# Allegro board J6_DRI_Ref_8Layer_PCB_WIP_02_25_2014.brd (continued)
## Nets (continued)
H_MMC2_DAT4_S1: RN30.4(R4A)
H_MMC2_DAT5: RN30.6(R3B) U52.M7(GPMC_A20/MMC2_DAT5/GPMC_A14/VIN)
H_MMC2_DAT5_S1: RN30.3(R3A)
H_MMC2_DAT6: RN30.7(R2B) U52.J5(GPMC_A21/MMC2_DAT6/GPMC_A15/VIN)
H_MMC2_DAT6_S1: RN30.2(R2A)
H_MMC2_DAT7: RN30.8(R1B) U52.K6(GPMC_A22/MMC2_DAT7/GPMC_A16/VIN)
H_MMC2_DAT7_S1: RN30.1(R1A)
H_MMC3_CLK: R859.1 U52.AD4(MMC3_CLK/USB3_ULPI_D5/VIN2B_D7/)
H_MMC3_CLK_S1: R859.2
H_MMC3_CMD: U52.AC4(MMC3_CMD/SPI3_SCLK/USB3_ULPI_D4)
H_MMC3_DAT0: U52.AC7(MMC3_DAT0/SPI3_D1/UART5_RXD/USB)
H_MMC3_DAT1: U52.AC6(MMC3_DAT1/SPI3_D0/UART5_TXD/USB)
H_MMC3_DAT2: U52.AC9(MMC3_DAT2/SPI3_CS0/UART5_CTSN/U)
H_MMC3_DAT3: U52.AC3(MMC3_DAT3/SPI3_CS1/UART5_RTSN/U)
H_MMC3_DAT4: U52.AC8(MMC3_DAT4/SPI4_SCLK/UART10_RXD/)
H_MMC3_DAT5: U52.AD6(MMC3_DAT5/SPI4_D1/UART10_TXD/US)
H_MMC3_DAT6: U52.AB8(MMC3_DAT6/SPI4_D0/UART10_CTSN/U)
H_MMC3_DAT7: U52.AB5(MMC3_DAT7/SPI4_CS0/UART10_RTSN/)
H_MMC4_CLK: R651.2 U52.E25(UART1_CTSN/UART9_RXD/MMC4_CLK/G)
H_MMC4_CLK_S1: R651.1
H_MMC4_CMD: U52.C27(UART1_RTSN/UART9_TXD/MMC4_CMD/G)
H_MMC4_DAT0: U52.D28(UART2_RXD/UART3_CTSN/UART3_RCTX)
H_MMC4_DAT1: U52.D26(UART2_TXD/UART3_RTSN/UART3_SD/M)
H_MMC4_DAT2: U52.D27(UART2_CTSN/UART3_IRRX/MMC4_DAT2)
H_MMC4_DAT3: U52.C28(UART2_RTSN/UART3_TXD/UART3_IRTX)
H_NMIN: R245.1 R632.2 U52.D21(NMIN)
H_ON_OFF: R216.2 U52.Y11(ON_OFF)
H_OSC0_RTN: C126.2 C128.2 U52.AF15(VSSA_OSC0)
H_OSC0_XIN: C128.1 U52.AE15(XI_OSC0) Y6.1
H_OSC0_XOUT: C126.1 U52.AD15(X0_OSC0) Y6.2
H_OSC1_RTN: C123.2 C124.2 U52.AC14(VSSA_OSC1) Y5.2 Y5.4
H_OSC1_XIN: C123.1 U52.AC15(XI_OSC1) Y5.1
H_OSC1_XOUT: C124.1 U52.AC13(XO_OSC1) Y5.3
H_OSCRTC_XIN: C113.1 U52.AE14(RTC_OSC_XI_CLKIN32) Y3.4
H_OSCRTC_XOUT: C106.1 U52.AD14(RTC_OSC_XO) Y3.1
H_PCIE_RXN0: U52.AG13(PCIE_RXN0)
H_PCIE_RXN1: U52.AG11(PCIE_RXN1)
H_PCIE_RXP0: U52.AH13(PCIE_RXP0)
H_PCIE_RXP1: U52.AH11(PCIE_RXP1)
H_PCIE_TXN0: U52.AG14(PCIE_TXN0)
H_PCIE_TXN1: U52.AG12(PCIE_TXN1)
H_PCIE_TXP0: U52.AH14(PCIE_TXP0)
H_PCIE_TXP1: U52.AH12(PCIE_TXP1)
H_POR_N: C550.1 R269.2 TP60.1(TP) U52.F22(PORZ) U62.4(Y)
H_QSPI1_CS0: R131.1 U18.7(C\S\)
H_QSPI1_D0: U18.15(SI/IO0) U52.U1(GPMC_A16/QSPI1_D0/VIN4A_D9/GPIO)
H_QSPI1_D1: U18.8(SO/IO1) U52.P3(GPMC_A17/QSPI1_D1/VIN4A_D10/GPI)
H_QSPI1_D2: R442.2 U18.9(W\P\/IO2) U52.U2(GPMC_A15/QSPI1_D2/VIN4A_D8/TIME)
H_QSPI1_D3: R128.2 U18.1(H\O\L\D\/IO3) U52.T2(GPMC_A14/QSPI1_D3/VIN4A_VSYNC0/)
H_QSPI1_RTCLK: R727.2 U52.R3(GPMC_A13/QSPI1_RTCLK/VIN4A_HSYN)
H_QSPI1_SCLK: R963.2 U52.R2(GPMC_A18/QSPI1_SCLK/VIN4A_D11/G)
H_QSPI1_SCLK_23254155: R727.1 R728.2
H_QSPI1_SCLK_S1: R963.1
H_QSPI1_SCLK_S1_23254130: R728.1 U18.16(SCLK)
H_RESET_N: C553.1 TP59.1(TP) U52.E23(RESETN)
H_RGMII0_RXC: R917.2 U52.U5(RGMII0_RXC/RMII1_TXEN/MII0_TXCL)
H_RGMII0_RXC_S1: R917.1
H_RGMII0_RXCTL: R918.2 U52.V5(RGMII0_RXCTL/RMII1_TXD1/MII0_TX)
H_RGMII0_RXCTL_S1: R918.1
H_RGMII0_RXD0: R919.2 U52.W2(RGMII0_RXD0/RMII0_TXD0/MII0_TXD)
H_RGMII0_RXD0_S1: R919.1
H_RGMII0_RXD1: R920.2 U52.Y2(RGMII0_RXD1/RMII0_TXD1/MII0_TXD)
H_RGMII0_RXD1_S1: R920.1
H_RGMII0_RXD2: R921.2 U52.V3(RGMII0_RXD2/RMII0_TXEN/MII0_TXE)
H_RGMII0_RXD2_S1: R921.1
H_RGMII0_RXD3: R922.2 U52.V4(RGMII0_RXD3/RMII1_TXD0/MII0_TXD)
H_RGMII0_RXD3_S1: R922.1
H_RGMII0_TD0: R925.2 U52.U6(RGMII0_TXD0/RMII0_RXD0/MII0_RXD)
H_RGMII0_TD0_S1: R925.1
H_RGMII0_TD1: R926.2 U52.V6(RGMII0_TXD1/RMII0_RXD1/MII0_RXD)
H_RGMII0_TD1_S1: R926.1
H_RGMII0_TD2: R927.2 U52.U7(RGMII0_TXD2/RMII0_RXER/MII0_RXE)
H_RGMII0_TD2_S1: R927.1
H_RGMII0_TD3: R928.2 U52.V7(RGMII0_TXD3/RMII0_CRS/MII0_CRS/)
H_RGMII0_TD3_S1: R928.1
H_RGMII0_TXC: R923.2 U52.W9(RGMII0_TXC/UART3_CTSN/RMII1_RXD)
H_RGMII0_TXC_S1: R923.1
H_RGMII0_TXCTL: R924.2 U52.V9(RGMII0_TXCTL/UART3_RTSN/RMII1_R)
H_RGMII0_TXCTL_S1: R924.1
H_RMII_50MHZ_CLK: R929.2 U52.U3(RMII_MHZ_50_CLK/VIN2A_D11/GPIO5)
H_RMII_50MHZ_CLK_S1: R929.1
H_RSTOUT_N: R256.2 R417.1 R650.2 R864.1 TP58.1(TP) U18.3(R\E\S\E\T\/RFU) U52.F23(RSTOUTN) U59.33(R\E\S\E\T\) U130.2(A) U132.8(RESETB)
H_RSV_Y5: U52.Y5(RSV_Y5)
H_SATA1_TXN0: U52.AG9(SATA1_RXP0) U52.AG10(SATA1_TXN0) U52.AG15(LJCB_CLKP)
H_SATA1_TXP0: U52.AH9(SATA1_RXN0) U52.AH10(SATA1_TXP0)
H_UART1_DBG_RX1: U52.B27(UART1_RXD/MMC4_SDCD/GPIO7_22)
H_UART1_DBG_TX1: U52.C26(UART1_TXD/MMC4_SDWP/GPIO7_23)
H_UART3_CTS: U52.G17(SPI2_D0/UART3_CTSN/UART5_RXD/GP)
H_UART3_RTS: U52.B24(SPI2_CS0/UART3_RTSN/UART5_TXD/G)
H_UART3_RXD: U52.A26(SPI2_SCLK/UART3_RXD/GPIO7_14)
H_UART3_TXD: U52.B22(SPI2_D1/UART3_TXD/GPIO7_15)
H_UART4_LIN_RXD: U52.B21(SPI1_CS2/UART4_RXD/MMC3_SDCD/SP)
H_UART4_LIN_TXD: U52.B20(SPI1_CS3/UART4_TXD/MMC3_SDWP/SP)
H_USB1_DM: FL1.4 U52.AC12(USB1_DM)
H_USB1_DP: FL1.1 U52.AD12(USB1_DP)
H_USB1_DRV_VBUS: R481.2 U36.4(EN) U52.AB10(USB1_DRVVBUS)
H_USB2_DM: FL4.4 U52.AF11(USB2_DM)
H_USB2_DP: FL4.1 U52.AE11(USB2_DP)
H_USB2_DRV_VBUS: R532.2 U43.4(EN) U52.AC10(USB2_DRVVBUS)
H_VIN1A_CLK0: R961.2 U52.AG8(VIN1A_CLK0/VOUT3_D16/VOUT3_FLD/)
H_VIN1A_CLK0_S1: R961.1
H_VIN1A_D0: U52.AE8(VIN1A_D0/VOUT3_D7/VOUT3_D23/UAR)
H_VIN1A_D1: U52.AD8(VIN1A_D1/VOUT3_D6/VOUT3_D22/UAR)
H_VIN1A_D2: U52.AG7(VIN1A_D2/VOUT3_D5/VOUT3_D21/UAR)
H_VIN1A_D3: U52.AH6(VIN1A_D3/VOUT3_D4/VOUT3_D20/UAR)
H_VIN1A_D4: U52.AH3(VIN1A_D4/VOUT3_D3/VOUT3_D19/EHR)
H_VIN1A_D5: U52.AH5(VIN1A_D5/VOUT3_D2/VOUT3_D18/EHR)
H_VIN1A_D6: U52.AG6(VIN1A_D6/VOUT3_D1/VOUT3_D17/EQE)
H_VIN1A_D7: U52.AH4(VIN1A_D7/VOUT3_D0/VOUT3_D16/EQE)
H_VIN1A_D8: U52.AG4(VIN1A_D8/VIN1B_D7/VOUT3_D15/KBD)
H_VIN1A_D9: U52.AG2(VIN1A_D9/VIN1B_D6/VOUT3_D14/KBD)
H_VIN1A_D10: U52.AG3(VIN1A_D10/VIN1B_D5/VOUT3_D13/KB)
H_VIN1A_D11: U52.AG5(VIN1A_D11/VIN1B_D4/VOUT3_D12/GP)
H_VIN1A_D12: U52.AF2(VIN1A_D12/VIN1B_D3/USB3_ULPI_D7)
H_VIN1A_D13: U52.AF6(VIN1A_D13/VIN1B_D2/USB3_ULPI_D6)
H_VIN1A_D14: U52.AF3(VIN1A_D14/VIN1B_D1/USB3_ULPI_D5)
H_VIN1A_D15: U52.AF4(VIN1A_D15/VIN1B_D0/USB3_ULPI_D4)
H_VIN1A_D16: U52.AF1(VIN1A_D16/VIN1B_D7/USB3_ULPI_D3)
H_VIN1A_D17: U52.AE3(VIN1A_D17/VIN1B_D6/USB3_ULPI_D2)
H_VIN1A_D18: U52.AE5(VIN1A_D18/VIN1B_D5/USB3_ULPI_D1)
H_VIN1A_D19: U52.AE1(VIN1A_D19/VIN1B_D4/USB3_ULPI_D0)
H_VIN1A_D20: U52.AE2(VIN1A_D20/VIN1B_D3/USB3_ULPI_NX)
H_VIN1A_D21: U52.AE6(VIN1A_D21/VIN1B_D2/USB3_ULPI_DI)
H_VIN1A_D22: U52.AD2(VIN1A_D22/VIN1B_D1/USB3_ULPI_ST)
H_VIN1A_D23: U52.AD3(VIN1A_D23/VIN1B_D0/USB3_ULPI_CL)
H_VIN1A_DE0: U52.AD9(VIN1A_DE0/VIN1B_HSYNC1/VOUT3_D1)
H_VIN1A_FLD0: U52.AF9(VIN1A_FLD0/VIN1B_VSYNC1/VOUT3_C)
H_VIN1A_HSYNC0: U52.AE9(VIN1A_HSYNC0/VIN1B_FLD1/VOUT3_H)
H_VIN1A_VSYNC0: U52.AF8(VIN1A_VSYNC0/VIN1B_DE1/VOUT3_VS)
H_VIN1B_CLK1: R960.2 U52.AH7(VIN1B_CLK1/VIN3A_CLK0/GPIO2_31)
H_VIN1B_CLK1_S1: R960.1
H_VIN2A_CLK0: R962.2 U52.E1(VIN2A_CLK0/VOUT2_FLD/EMU5/KBD_R)
H_VIN2A_CLK0_S1: R962.1
H_VIN2A_D0: U52.F2(VIN2A_D0/VOUT2_D23/EMU10/UART9_)
H_VIN2A_D1: U52.F3(VIN2A_D1/VOUT2_D22/EMU11/UART9_)
H_VIN2A_D2: U52.D1(VIN2A_D2/VOUT2_D21/EMU12/UART10)
H_VIN2A_D3: U52.E2(VIN2A_D3/VOUT2_D20/EMU13/UART10)
H_VIN2A_D4: U52.D2(VIN2A_D4/VOUT2_D19/EMU14/UART10)
H_VIN2A_D5: U52.F4(VIN2A_D5/VOUT2_D18/EMU15/UART10)
H_VIN2A_D6: U52.C1(VIN2A_D6/VOUT2_D17/EMU16/MII1_R)
H_VIN2A_D7: U52.E4(VIN2A_D7/VOUT2_D16/EMU17/MII1_R)
H_VIN2A_D8: U52.F5(VIN2A_D8/VOUT2_D15/EMU18/MII1_R)
H_VIN2A_D9: U52.E6(VIN2A_D9/VOUT2_D14/EMU19/MII1_R)
H_VIN2A_D10: U52.D3(VIN2A_D10/MDIO_MCLK/VOUT2_D13/K)
H_VIN2A_D11: U52.F6(VIN2A_D11/MDIO_D/VOUT2_D12/KBD_)
H_VIN2A_D12: U52.D5(VIN2A_D12/RGMII1_TXC/VOUT2_D11/)
H_VIN2A_D13: U52.C2(VIN2A_D13/RGMII1_TXCTL/VOUT2_D1)
H_VIN2A_D14: U52.C3(VIN2A_D14/RGMII1_TXD3/VOUT2_D9/)
H_VIN2A_D15: U52.C4(VIN2A_D15/RGMII1_TXD2/VOUT2_D8/)
H_VIN2A_D16: U52.B2(VIN2A_D16/VIN2B_D7/RGMII1_TXD1/)
H_VIN2A_D17: U52.D6(VIN2A_D17/VIN2B_D6/RGMII1_TXD0/)
H_VIN2A_D18: U52.C5(VIN2A_D18/VIN2B_D5/RGMII1_RXC/V)
H_VIN2A_D19: U52.A3(VIN2A_D19/VIN2B_D4/RGMII1_RXCTL)
H_VIN2A_D20: U52.B3(VIN2A_D20/VIN2B_D3/RGMII1_RXD3/)
H_VIN2A_D21: U52.B4(VIN2A_D21/VIN2B_D2/RGMII1_RXD2/)
H_VIN2A_D22: U52.B5(VIN2A_D22/VIN2B_D1/RGMII1_RXD1/)
H_VIN2A_D23: U52.A4(VIN2A_D23/VIN2B_D0/RGMII1_RXD0/)
H_VIN2A_DE0: U52.G2(VIN2A_DE0/VIN2A_FLD0/VIN2B_FLD1)
H_VIN2A_FLD0: U52.H7(VIN2A_FLD0/VIN2B_CLK1/VOUT2_CLK)
H_VIN2A_HSYNC0: U52.G1(VIN2A_HSYNC0/VIN2B_HSYNC1/VOUT2)
H_VIN2A_VSYNC0: U52.G6(VIN2A_VSYNC0/VIN2B_VSYNC1/VOUT2)
H_VOUT1_CLK: R834.2 U52.D11(VOUT1_CLK/VIN4A_FLD0/VIN3A_FLD0)
H_VOUT1_D0: RN20.5(R4B) U52.F11(VOUT1_D0/UART5_RXD/VIN4A_D16/VI)
H_VOUT1_D1: RN20.6(R3B) U52.G10(VOUT1_D1/UART5_TXD/VIN4A_D17/VI)
H_VOUT1_D2: RN20.7(R2B) U52.F10(VOUT1_D2/EMU2/VIN4A_D18/VIN3A_D)
H_VOUT1_D3: RN20.8(R1B) U52.G11(VOUT1_D3/EMU5/VIN4A_D19/VIN3A_D)
H_VOUT1_D4: RN21.5(R4B) U52.E9(VOUT1_D4/EMU6/VIN4A_D20/VIN3A_D)
H_VOUT1_D5: RN21.6(R3B) U52.F9(VOUT1_D5/EMU7/VIN4A_D21/VIN3A_D)
H_VOUT1_D6: RN21.7(R2B) U52.F8(VOUT1_D6/EMU8/VIN4A_D22/VIN3A_D)
H_VOUT1_D7: RN21.8(R1B) U52.E7(VOUT1_D7/EMU9/VIN4A_D23/VIN3A_D)
H_VOUT1_D8: RN22.5(R4B) U52.E8(VOUT1_D8/UART6_RXD/VIN4A_D8/VIN)
H_VOUT1_D9: RN22.6(R3B) U52.D9(VOUT1_D9/UART6_TXD/VIN4A_D9/VIN)
H_VOUT1_D10: RN22.7(R2B) U52.D7(VOUT1_D10/EMU3/VIN4A_D10/VIN3A_)
H_VOUT1_D11: RN22.8(R1B) U52.D8(VOUT1_D11/EMU10/VIN4A_D11/VIN3A)
H_VOUT1_D12: RN23.5(R4B) U52.A5(VOUT1_D12/EMU11/VIN4A_D12/VIN3A)
H_VOUT1_D13: RN23.6(R3B) U52.C6(VOUT1_D13/EMU12/VIN4A_D13/VIN3A)
H_VOUT1_D14: RN23.7(R2B) U52.C8(VOUT1_D14/EMU13/VIN4A_D14/VIN3A)
H_VOUT1_D15: RN23.8(R1B) U52.C7(VOUT1_D15/EMU14/VIN4A_D15/VIN3A)
H_VOUT1_D16: RN24.5(R4B) U52.B7(VOUT1_D16/UART7_RXD/VIN4A_D0/VI)
H_VOUT1_D17: RN24.6(R3B) U52.B8(VOUT1_D17/UART7_TXD/VIN4A_D1/VI)
H_VOUT1_D18: RN24.7(R2B) U52.A7(VOUT1_D18/EMU4/VIN4A_D2/VIN3A_D)
H_VOUT1_D19: RN24.8(R1B) U52.A8(VOUT1_D19/EMU15/VIN4A_D3/VIN3A_)
H_VOUT1_D20: RN25.5(R4B) U52.C9(VOUT1_D20/EMU16/VIN4A_D4/VIN3A_)
H_VOUT1_D21: RN25.6(R3B) U52.A9(VOUT1_D21/EMU17/VIN4A_D5/VIN3A_)
H_VOUT1_D22: RN25.7(R2B) U52.B9(VOUT1_D22/EMU18/VIN4A_D6/VIN3A_)
H_VOUT1_D23: RN25.8(R1B) U52.A10(VOUT1_D23/EMU19/VIN4A_D7/VIN3A_)
H_VOUT1_DE: R835.2 U52.B10(VOUT1_DE/VIN4A_DE0/VIN3A_DE0/SP)
H_VOUT1_HSYNC: R837.2 U52.C11(VOUT1_HSYNC/VIN4A_HSYNC0/VIN3A_)
H_VOUT1_VSYNC: R836.2 U52.E11(VOUT1_VSYNC/VIN4A_VSYNC0/VIN3A_)
H_WAKEUP0: TP54.1(TP) U52.AD17(WAKEUP0)
H_WAKEUP2: C535.1 R636.1 TP52.1(TP) U52.AB16(WAKEUP2)
H_WAKEUP3: R620.1 TP55.1(TP) U52.AC16(WAKEUP3)
H_XREF_CLK0: U52.D18(XREF_CLK0/MCASP2_AXR8/MCASP1_AX)
H_XREF_CLK1: U52.E17(XREF_CLK1/MCASP2_AXR9/MCASP1_AX)
H_XREF_CLK2: U52.B26(REF_CLK2/MCASP2_AXR10/MCASP1_AX)
H_XREF_CLK3: U52.C23(XREF_CLK3/MCASP2_AXR11/MCASP1_A)
HSGMLAN_BUS+: R238.1 R850.1 R941.1
HSGMLAN_BUS-: R255.2 R851.1 R942.1
I2C1_SCL: U50.6(SCL2) U59.1(SCL) U105.6(SCL) U117.1(SCL)
I2C1_SDA: U50.5(SDA2) U59.2(SDA) U105.5(SDA) U117.6(SDA)
I2C2_SCL: U3.8(SCL) U132.21(SCL)
I2C2_SDA: U3.9(SDA) U132.22(SDA)
I2C3_SCL: R865.1
I2C3_SDA: R420.2
I2C_EEPROM_WP: R569.2 R757.2 U105.7(WP)
INIC_DBG_ERR_BOOTN: P1.29
INIC_DBG_RSTN: P1.31
INIC_TCK: P1.35
INIC_TDI: P1.39
INIC_TDO: P1.37
INIC_TMS: P1.33
LIN_EN: R935.2
LIN_INH: TP76.1 U122.8(INH)
LIN_WAKE: TP77.1 U122.3(NWAKE)
LT_PMIC_RESET_OUT: R782.1 U101.3(A2)
LVL_SHIFT_V: U100.10(OE)
MCA1_ACLKX: U48.4(1A1)
MCA1_AFSX: U48.5(1A2)
MCA1_AXR0: U35.6(A4)
MCA1_AXR1: U48.6(2A1)
MCA7_AXR0: U35.9(A7)
MCA7_AXR1: U41.6(2A1)
MCA7_CLKX: U41.4(1A1)
MCA7_FSX: U41.5(1A2)
MCASP1_ENN: R599.2 R766.2 U35.22(OEN) U46.22(OEN) U48.14(2O\E\) U48.15(1O\E\)
MCU_DBG_RESETN: P1.24
MCU_DCAN_RX: U123.4(RXD)
MCU_DCAN_STB: R849.1 U123.8(STB)
MCU_DCAN_TX: R848.1 U123.1(TXD)
MCU_EVT0: P1.28
MCU_FLMD0: P1.26
MCU_FLMD1: P1.20
MCU_LIN_EN: R936.2
MCU_LIN_RXD: R934.2
MCU_LIN_TXD: R938.2
MCU_RDY: P1.30
MCU_RESET_OUT: R940.1
MCU_TCK: P1.36
MCU_TDI: P1.40
MCU_TDO: P1.38
MCU_TMS: P1.34
MCU_TRSTN: P1.32
MCU_TVD: P1.22
MIC_IN+: R801.1 R802.1
MIC_IN-: R800.1
MMC2_CLK: R433.2 U121.M6(CLK)
MMC2_CMD: R410.2 U121.M5(CMD)
MMC2_DAT0: R404.2 U121.A3(DAT0)
MMC2_DAT1: R422.2 U121.A4(DAT1)
MMC2_DAT2: R426.2 U121.A5(DAT2)
MMC2_DAT3: R406.2 U121.B2(DAT3)
MMC2_DAT4: R405.2 U121.B3(DAT4)
MMC2_DAT5: R414.2 U121.B4(DAT5)
MMC2_DAT6: R423.2 U121.B5(DAT6)
MMC2_DAT7: R428.2 U121.B6(DAT7)
MMC4_CLK: R587.2 U104.4(B)
MMC4_CMD: R520.2 U100.16(B4)
MMC4_DAT0: R521.2 U100.15(B5)
MMC4_DAT1: R522.2 U100.14(B6)
MMC4_DAT2: R523.2 U100.13(B7)
MMC4_DAT3: R524.2 U100.12(B8)
PCM_CLK: P9.52 U41.13(1B1)
PCM_DIN: P9.56 U41.11(2B1)
PCM_DOUT: P9.58 U35.15(B7)
PCM_FSYNC: P9.54 U41.12(1B2)
PHA: C300.1 L6.1 Q1.1(S1) Q1.2(S2) Q1.3(S3) Q3.5(D1) R126.2 U23.7(PHA)
PHB: C299.1 L7.1 Q2.1(S1) Q2.2(S2) Q2.3(S3) Q4.5(D1) R127.2 U23.32(PHB)
PMIC_32K_CLKOUT: R222.1 U45.M11(CLK32KGO)
PMIC_BOOT0: R518.1 R785.2 U45.L3(BOOT0)
PMIC_BOOT1: R513.1 R514.2 U45.K7(BOOT1)
PMIC_GPIO_0: R205.1 U45.B12(GPIO_0)
PMIC_GPIO_1: R191.1 R567.2 U45.C13(GPIO_1/VBUSDET)
PMIC_GPIO_2: R206.1 R783.1 U45.A12(GPIO_2/REGEN2)
PMIC_GPIO_3: R535.1 U45.H9(GPIO_3)
PMIC_GPIO_4_6: R473.1 U45.K10(GPIO_4/SYSEN1) U92.3(ON)
PMIC_GPIO_5: R565.1 U45.C10(GPIO_5/CLK32KGO)
PMIC_GPIO_6_4: R273.2 U45.N11(GPIO_6/SYSEN2) U63.15(EN)
PMIC_GPIO_7: R534.2 R537.1 U45.G9(GPIO_7/POWERHOLD)
PMIC_INT: R605.1 TP57.1(TP) U52.AC17(WAKEUP1) U101.2(A1)
PMIC_OFF: R204.2 R211.1 R216.1 U110.2(I)
PMIC_PWRDOWN: R483.1 R516.2 U45.K8(PWRDOWN)
PMIC_REGEN1: R784.1 TP41.1 U45.F8(REGEN1)
PMIC_RESET_IN: R153.2 R533.2 U37.1(R\E\S\E\T) U45.K9(RESET_IN)
PMIC_RESET_OUT: R782.2 R783.2 R784.2 U62.1(B)
PWRON: R208.2 R592.1 U45.G8(PWRON)
RPWRON: R194.2 R570.1 U45.C11(RPWRON)
RTC_PORZ: R530.2 U44.1(R\E\S\E\T) U52.AB17(RTC_PORZ)
SLEEP_CLK: P9.1 R222.2
SMPS_7: C409.2 L18.1
SMPS_8: C328.2 L9.1
SW1: L17.2 U45.E11(SMPS1_SW_1) U45.E12(SMPS1_SW_2) U45.E13(SMPS1_SW_3)
SW2: L15.2 U45.F11(SMPS2_SW_1) U45.F12(SMPS2_SW_2) U45.F13(SMPS2_SW_3)
SW3: L13.2 U45.J11(SMPS3_SW_1) U45.J12(SMPS3_SW_2) U45.J13(SMPS3_SW_3)
SW4: L16.2 U45.G1(SMPS4_SW_1) U45.G2(SMPS4_SW_2) U45.G3(SMPS4_SW_3)
SW5: L14.2 U45.H1(SMPS5_SW_1) U45.H2(SMPS5_SW_2) U45.H3(SMPS5_SW_3)
SW6: L11.2 U45.M5(SMPS6_SW_1) U45.N5(SMPS6_SW)
SW7: L18.2 U45.D1(SMPS7_SW_1) U45.D2(SMPS7_SW_2) U45.D3(SMPS7_SW_3)
SW8: L9.2 U45.M10(SMPS8_SW) U45.N10(SMPS8_SW_1)
SW9: L10.2 U45.M7(SMPS9_SW) U45.N7(SMPS9_SW_1)
TLIN1: R830.2 U122.6(LIN)
TPS43351_GC2: Q5.1(G) U23.4(GC2)
UART3_CTS: U35.8(A6)
UART3_RTS: U46.9(A7)
UART3_RXD: U35.7(A5)
UART3_TXD: U46.10(A8)
UART4_LIN_RXD: R933.2
UART4_LIN_TXD: R937.2
USB1_ID: U73.5(ID)
USB1_VBUS_OCN: R771.1 TP27.1 U36.5(OCN)
USB2_ID: U72.5(ID)
USB2_VBUS_OCN: R770.1 TP39.1 U43.5(OCN)
VAIC_AVDD_DAC3V3: C141.1 C142.1 C144.1 L21.1 U59.25(AVDD_DAC)
VAIC_DRVDD_3V3: C151.1 C152.1 C565.1 C566.1 C567.1 L22.1 U59.16(DRVDD.1) U59.17(DRVDD.2) U59.24(DRVDD.3)
VAIC_DVDD_1V8: C133.1 C134.1 U55.5(OUT) U59.36(DVDD.1)
VAIC_IOVDD_3V3: C130.1 C132.1 L19.2 U59.44(IOVDD)
VCAP_VBBLDO_DSPEVE: C477.1 U52.K9(CAP_VBBLDO_DSPEVE)
VCAP_VBBLDO_GPU: C501.1 U52.Y14(CAP_VBBLDO_GPU)
VCAP_VBBLDO_IVA: C519.1 U52.R20(CAP_VBBLDO_IVA)
VCAP_VBBLDO_MPU: C509.1 U52.J16(CAP_VBBLDO_MPU)
VCAP_VDDRAM_CORE1: C468.1 U52.L9(CAP_VDDRAM_CORE1)
VCAP_VDDRAM_CORE2: C517.1 U52.J19(CAP_VDDRAM_CORE2)
VCAP_VDDRAM_CORE3: C506.1 U52.Y15(CAP_VDDRAM_CORE3)
VCAP_VDDRAM_CORE4: C516.1 U52.P19(CAP_VDDRAM_CORE4)
VCAP_VDDRAM_CORE5: C512.1 U52.Y16(CAP_VDDRAM_CORE5)
VCAP_VDDRAM_DSPEVE1: C481.1 U52.J10(CAP_VDDRAM_DSPEVE1)
VCAP_VDDRAM_DSPEVE2: C462.1 U52.J9(CAP_VDDRAM_DSPEVE2)
VCAP_VDDRAM_GPU: C480.1 U52.Y13(CAP_VDDRAM_GPU)
VCAP_VDDRAM_IVA: C529.1 U52.T20(CAP_VDDRAM_IVA)
VCAP_VDDRAM_MPU1: C504.1 U52.K16(CAP_VDDRAM_MPU1)
VCAP_VDDRAM_MPU2: C520.1 U52.K19(CAP_VDDRAM_MPU2)
VDAC_3V3: C131.1 C153.1 C536.1 E8.3 L19.1 L21.2 L22.2 R249.1 R654.1 R659.1 R664.1 R668.1 U55.1(IN)
VEVM_1V8: C800.2 C810.2 E10.1 L23.1 P9.8 R548.1 R600.1 R842.2 R843.2 R844.2 R845.2 U132.20(DVDD)
VEVM_3V3: C67.1 C71.1 C74.1 C156.1 C293.1 C302.2 C330.1 C331.1 C338.2 C341.2 C342.2 C344.1 C346.2 C351.1 C353.2 C354.2 C358.1 C375.2 C376.2 C379.2 C380.2 C381.2 C404.1 C408.2 C441.1 C446.1 C459.2 C479.1 C513.2 C523.2 C573.1 C683.1 C696.1 C733.2 C734.2 C785.1 C786.1 C801.2 L2.2 L3.1 P5.1 P5.2 R1.2 R8.1 R14.1 R15.1 R16.1 R17.1 R18.1 R19.1 R20.1 R22.1 R80.1 R81.1 R82.1 R86.1 R87.1 R88.1 R89.1 R90.1 R91.1 R92.1 R93.1 R94.1 R95.1 R113.1 R114.1 R115.1 R128.1 R131.2 R134.1 R140.2 R143.2 R151.1 R153.1 R193.1 R194.1 R207.1 R208.1 R209.1 R272.1 R301.2 R302.2 R307.2 R327.1 R332.1 R407.2 R429.2 R442.1 R516.1 R519.1 R520.1 R521.1 R522.1 R523.1 R524.1 R528.1 R534.1 R549.1 R573.1 R575.1 R577.1 R581.1 R583.1 R584.1 R587.1 R596.2 R603.1 R618.1 R623.2 R624.1 R629.1 R632.1 R633.1 R650.1 R652.1 R757.1 R758.1 R759.1 R766.1 R770.2 R771.2 R774.1 R828.1 R829.1 R831.1 R839.1 R840.1 R841.1 R866.2 R867.2 R912.1 R914.2 R944.1 R945.1 R959.2 U6.5(VCC) U18.2(VCC) U18.14(VIO/RFU) U23.11(SA2) U35.1(VCCA) U37.6(VDD) U41.1(VCCA) U44.6(VDD) U45.C4(LDO9_IN) U45.C5(LDOLN_IN) U45.D11(SMPS1_IN_1) U45.D12(SMPS1_IN_2) U45.D13(SMPS1_IN_3) U45.E1(SMPS7_IN_B1_1) U45.E2(SMPS7_IN_B1_2) U45.E3(SMPS7_IN_B1_3) U45.F1(SMPS4_IN_1) U45.F2(SMPS4_IN_2) U45.F3(SMPS4_IN_3) U45.G11(SMPS2_IN_1) U45.G12(SMPS2_IN_2) U45.G13(SMPS2_IN_3) U45.H11(SMPS3_IN_1) U45.H12(SMPS3_IN_2) U45.H13(SMPS3_IN_3) U45.J1(SMPS5_IN_1) U45.J2(SMPS5_IN_2) U45.J3(SMPS5_IN_3) U45.L12(LDO34_IN) U45.L13(LDO34_IN_1) U45.M6(SMPS6_IN) U45.M8(SMPS9_IN) U45.M9(SMPS8_IN) U45.N6(SMPS6_IN_1) U45.N8(SMPS9_IN_1) U45.N9(SMPS8_IN_1) U46.1(VCCA) U46.2(DIR) U48.1(VCCA) U62.5(VCC) U63.1(VIN.2) U63.2(VIN.3) U63.16(VIN.1) U92.1(VIN.1) U92.2(VIN.2) U100.19(VCCB) U101.1(VCCA) U102.6(VDD) U104.6(VCCB) U105.8(VCC) U117.5(V+) U129.5(VCC) U130.5(VCC) U132.10(IO_DVDD)
VEVM_3V3_SD: C14.1 C15.1 C16.1 C233.1 C693.1 C787.1 P14.4(VDD) R774.2 U77.1(VCC) U78.1(VCC) U79.1(VCC) U131.1(VCC)
VEVM_3V3_SW: C174.2 C319.1 E8.1 E11.1 R282.2 R283.2 U64.10(VIN) U92.7(VOUT.2) U92.8(VOUT.1)
VEVM_3V6: C503.1 C515.1 P9.5 P9.7 R244.1 U56.9(VOUT1) U56.10(VOUT2)
VEVM_5V0: C72.1 C77.1 C99.2 C301.2 C325.1 C340.1 C407.2 C531.1 C546.1 C720.1 R35.1 R135.1 R138.2 R147.2 U23.28(SB2) U36.2(IN1) U36.3(IN2) U43.2(IN1) U43.3(IN2) U45.A6(LDO12_IN) U45.A9(LDOUSB_IN2) U45.A10(LDO7USB_IN1) U54.3(VCC) U56.1(IN1) U56.2(IN2) U56.4(BIAS) U56.5(EN) U123.3(VCC)
VEVM_12V: C45.1 C47.1 C49.1 C50.1 C51.1 C52.1 C62.2 C63.2 Q1.5(D1) Q2.5(D1) Q5.3(S) U8.3 U23.38(VIN)
VID+: R943.2 R951.1
VID-: R955.1
VIDEO+: FL5.3
VIDEO-: FL5.2
VIO_PMIC: C434.2 C435.1 R192.2 R210.1 R533.1 U45.D9(VIO_IN) U101.8(VCCB)
VLVL_SHIFT_V: C332.1 C335.1 C345.1 C405.1 C411.1 C447.1 C448.1 C472.1 R548.2 R558.1 R559.1 R560.1 R561.1 R562.1 U35.23(VCCB#23) U35.24(VCCB#24) U41.16(VCCB) U46.23(VCCB#23) U46.24(VCCB#24) U48.16(VCCB) U100.2(VCCA) U104.1(VCCA)
VMCU_3V3: C721.1 R913.1 R939.1 U123.5(VIO/NC)
VMMC_3V3: C274.1 C280.1 R404.1 R405.1 R406.1 R407.1 R410.1 R414.1 R422.1 R423.1 R426.1 R428.1 R433.1 U121.C6(VDD.1) U121.M4(VDD.2) U121.N4(VDD.3) U121.P3(VDD.4) U121.P5(VDD.5)
VOUT1_CLK: R834.1 U3.10(PCLK)
VOUT1_D0: RN20.4(R4A) U3.43(B0/O4)
VOUT1_D1: RN20.3(R3A) U3.44(B1/I2S_DB/O5)
VOUT1_D2: J17.13(TR_CLK0) RN20.2(R2A) U3.45(B2)
VOUT1_D3: J17.25(TRD0.4) RN20.1(R1A) U3.46(B3)
VOUT1_D4: J17.27(TRD0.5) RN21.4(R4A) U3.47(B4)
VOUT1_D5: J17.29(TRD0.6) RN21.3(R3A) U3.48(B5)
VOUT1_D6: J17.31(TRD0.7) RN21.2(R2A) U3.1(B6)
VOUT1_D7: RN21.1(R1A)
VOUT1_D8: RN22.4(R4A) U3.35(G0/IO2)
VOUT1_D9: RN22.3(R3A) U3.36(G1/IO3)
VOUT1_D10: J17.17(TRD0.0) RN22.2(R2A) U3.37(G2)
VOUT1_D11: J17.35(TRD0.9) RN22.1(R1A) U3.38(G3)
VOUT1_D12: J17.37(TRD3.0) RN23.4(R4A) U3.39(G4)
VOUT1_D13: J17.39(TRD3.1) RN23.3(R3A) U3.40(G5)
VOUT1_D14: J17.41(TRD3.2) RN23.2(R2A) U3.41(G6)
VOUT1_D15: J17.43(TRD3.3) RN23.1(R1A) U3.42(G7)
VOUT1_D16: RN24.4(R4A) U3.25(R0/IO0)
VOUT1_D17: RN24.3(R3A) U3.26(R1/IO1)
VOUT1_D18: J17.23(TRD0.3) RN24.2(R2A) U3.27(R2)
VOUT1_D19: J17.45(TRD3.4) RN24.1(R1A) U3.28(R3)
VOUT1_D20: J17.47(TRD3.5) RN25.4(R4A) U3.29(R4)
VOUT1_D21: J17.49(TRD3.6) RN25.3(R3A) U3.32(R5)
VOUT1_D22: J17.51(TRD3.7) RN25.2(R2A) U3.33(R6)
VOUT1_D23: J17.53(TRD3.8) RN25.1(R1A) U3.34(R7)
VOUT1_DE: R835.1 U3.5(DE)
VOUT1_HSYNC: R837.1 U3.3(HS)
VOUT1_INTB: R846.1 U52.B11(VOUT1_FLD/VIN4A_CLK0/VIN3A_CLK0)
VOUT1_VSYNC: R836.1 U3.4(VS)
VOUT_D7: J17.33(TRD0.8) U3.2(B7)
VPP: TP51.1 U52.K14(VPP)
VREF_DBG: J17.1(VREF_DBG) J17.12(VREF_TR) R758.2
VREVM_3V3: P1.23 P1.25 R912.2
VRMCU_3V3: P1.27 R913.2
VRTC_OUT: R514.1 R567.1 R785.1
VTT_DDR: C164.1 C165.1 C166.1 C167.1 C175.1 C176.1 C180.1 C181.1 C188.2 C192.2 C202.2 C206.1 C207.1 C208.1 C209.1 C626.1 C627.1 C634.1 C635.1 C642.1 C643.1 C653.1 C654.1 C658.2 C660.1 C661.1 C662.1 C663.1 R286.2 R290.2 R689.2 RN2.5(R4B) RN2.6(R3B) RN2.7(R2B) RN2.8(R1B) RN3.5(R4B) RN3.6(R3B) RN3.7(R2B) RN3.8(R1B) RN4.5(R4B) RN4.6(R3B) RN4.7(R2B) RN4.8(R1B) RN5.5(R4B) RN5.6(R3B) RN5.7(R2B) RN5.8(R1B) RN6.5(R4B) RN6.6(R3B) RN6.7(R2B) RN6.8(R1B) RN7.5(R4B) RN7.6(R3B) RN7.7(R2B) RN7.8(R1B) RN12.5(R4B) RN12.6(R3B) RN12.7(R2B) RN12.8(R1B) RN13.5(R4B) RN13.6(R3B) RN13.7(R2B) RN13.8(R1B) RN14.5(R4B) RN14.6(R3B) RN14.7(R2B) RN14.8(R1B) RN15.5(R4B) RN15.6(R3B) RN15.7(R2B) RN15.8(R1B) RN16.5(R4B) RN16.6(R3B) RN16.7(R2B) RN16.8(R1B) RN17.5(R4B) RN17.6(R3B) RN17.7(R2B) RN17.8(R1B) U64.3(VO)
VUSB_3V3: C433.1 C439.1 C440.1 C451.1 C489.1 U45.B9(LDOUSB_OUT) U52.AA12(VDDA33V_USB1) U52.Y12(VDDA33V_USB2)
WL_EN: P9.4 U46.19(B3)
WLAN_IRQ: P9.34 U35.21(B1)
XTAL1: C115.1 U45.A3(OSC16MIN) Y4.1(C1A) Y4.3(C2A)
XTAL2: C116.1 U45.A2(OSC16MOUT) Y4.2(C1B) Y4.5(C2B)
ZQ_DBYTE1: R694.1 U115.H8(ZQ)
ZQ_DBYTE2: R289.1 U69.H8(ZQ)
ZQ_DBYTE3: R695.1 U116.H8(ZQ)
ZQ_DBYTE4: R288.1 U68.H8(ZQ)
ZQ_DBYTE4_1: R693.1 U67.H8(ZQ)
N35610: R692.1 U65.L8(ZQ)
N35614: R691.1 U66.L8(ZQ)
N16995143: R593.1 R597.1 R600.2 U50.2(VREF1)
N17024050: R178.1 R528.2 U41.2(1DIR)
N17024419: R157.1 R519.2 U41.3(2DIR)
N17038912: R200.1 R584.2 U48.2(1DIR)
N17039180: R196.1 R581.2 U48.3(2DIR)
N17041540: R715.1 U35.14(B8) U35.20(B2)
N17041657: R714.2 U46.3(A1) U46.7(A5) U46.8(A6)
N17043188: F1.1 Q5.4(D) U8.1
N17182406: TP78.1 U23.16(ENA) U23.17(ENB)
N17213676: R463.2 U23.22(RT)
N17213686: C60.2 R126.1
N17213736: C61.2 R127.1
N17213790: C299.2 U23.34(CBB)
N17213808: R138.1 U23.24(PGB)
N17213830: C78.2 R145.2 R146.1 U23.27(FBB)
N17213836: C303.2 C304.2 U23.26(COMPB)
N17213838: C301.1 L7.2 R135.2 U23.29(SB1)
N17213987: C295.2 R454.2 U23.35(VREG)
N17214057: Q2.4(G) R450.1
N17214061: R146.2 R147.1
N17214151: C300.2 U23.5(CBA)
N17214159: R140.1 U23.15(PGA)
N17214195: C76.2 R144.1 R472.2 U23.12(FBA)
N17214201: C307.2 C309.2 U23.13(COMPA)
N17214229: C302.1 L6.2 R134.2 U23.10(SA1)
N17214255: R454.1 R455.2 U23.20(SYNC)
N17214311: C305.1 U23.14(SSA)
N17214457: R453.1 U23.1(VBAT)
N17214562: C314.1 U23.21(DLYAB)
N17214601: Q1.4(G) R451.1
N17214615: C306.1 U23.25(SSB)
N17214651: R143.1 R144.2
N17444583: C186.2 R291.2 R292.1 U64.1(REFIN)
N17444631: R282.1 U64.9(PGOOD)
N17444633: C179.2 R290.1 U64.5(VOSNS)
N17444649: R283.1 U64.7(EN)
N17551426: R209.2 R590.1 U45.D8(VBUS)
N17551447: U45.G6(RESET_OUT) U101.6(B2)
N17551455: C403.2 U45.C1(OSC16MCAP)
N17551519: R207.2 U45.A11(VCC_SENSE2)
N17551551: TP31.1 U45.J5(ENABLE1)
N17551822: R210.2 R589.1 TP43.1 U45.E6(NRESWARM)
N17551928: C100.2 U45.B7(VBG)
N17681908: R35.2 U92.4(VBIAS)
N18507369: C432.2 R193.2 U45.C7(VCC1)
N18740603: C157.2 R280.1 U63.7(COMP)
N18740978: R278.2 R279.1 U63.6(VSNS)
N18743331: C149.2 U63.13(BOOT)
N18763016: R277.2 U63.8(RT/CLK)
N18763017: C155.1 U63.9(SS/TR)
N18763019: C149.1 C150.1 L20.1 U63.10(PH.1) U63.11(PH.2) U63.12(PH.3)
N18763021: R272.2 TP61.1(TP) U63.14(PWRGD)
N19060121: J17.15(TGT_DETECT) R762.2
N19066656: R591.1 TP42.1 U45.B8(SYNC_TO_EXCLOCK)
N19176689: C579.2 R280.2
N19176787: C150.2 R276.2
N19184134: P9.12 TP49.1(TP)
N19184365: P9.14 TP46.1(TP)
N19184698: P9.16 TP44.1(TP)
N19185088: P9.73 TP23.1(TP)
N20019184: C601.1 R685.2 R688.2
N20082076: TP30.1 U45.K1(INT) U101.7(B1)
N20307647: TP24.1 U45.J7(POWERGOOD)
N21135894: C647.2 P12.3(RING) R702.1
N21136021: R249.2 R644.1 U59.43(SELECT)
N21136029: R671.2 U59.11(MIC3L) U59.14(MIC3R)
N21136035: C558.1 C575.1 R673.1 R675.1 R801.2
N21136037: C568.1 R672.1 R673.2
N21136043: R672.2 U59.13(MICBIAS)
N21136051: C558.2 R671.1
N21136104: C173.2 U59.3(LINE1L+)
N21136106: C168.2 P12.2(TIP) R287.1
N21136118: R281.1 U59.29(LEFT_LO+)
N21136820: C648.1 R800.2
N21136921: R257.1 R654.2 U59.45(MFP0)
N21136923: R260.1 R659.2 U59.46(MFP1)
N21136925: R262.1 R664.2 U59.47(MFP2)
N21136935: R254.2 U59.37(MCLK)
N21136951: R266.1 R668.2 U59.48(MFP3)
N21137001: C173.1 R802.2
N21137040: C647.1 R697.2
N21137042: R697.1 U59.31(RIGHT_LO+)
N21137044: C168.1 R281.2
N21262314: TP1.1 U72.1(VBUS_OUT.1) U72.2(VBUS_OUT.2)
N21262497: R302.1 U72.3(ENN)
N21262499: R307.1 U72.4(ACKN)
N21266752: C5.1 U3.20(DOUT+)
N21266761: C6.1 U3.19(DOUT-)
N21266764: C6.2 FL5.1
N21266767: C5.2 FL5.4
N21299491: C798.1 R956.2 U132.5(XTAL1/OSC) Y7.2
N21299495: C799.1 R956.1 U132.6(XTAL2) Y7.1
N21300352: R948.2 U132.25(HSYNC)
N21300357: R949.2 U132.24(VSYNC/PALI)
N21300366: RN32.5(R4B) U132.18(YOUT0)
N21300375: RN32.6(R3B) U132.17(YOUT1)
N21300384: RN32.7(R2B) U132.16(YOUT2)
N21300398: RN32.8(R1B) U132.15(YOUT3)
N21300482: RN33.5(R4B) U132.14(YOUT4)
N21300487: RN33.6(R3B) U132.13(YOUT5)
N21300492: RN33.7(R2B) U132.12(YOUT6)
N21300497: R958.1 R959.1 RN33.8(R1B) U132.11(YOUT7/I2CSEL)
N21300502: R957.2 U132.9(SCLK)
N21300554: C788.2 U132.1(AIP1A)
N21300935: C789.2 C791.1 U132.30(REFM)
N21300940: C790.2 C791.2 U132.29(REFP)
N21301555: C792.1 C793.1 C794.1 L23.2 U132.4(PLL_AVDD) U132.32(CH_AVDD)
N21358273: C525.1 R238.2 R255.1
N21358507: R615.1 U54.8(STB) U110.4(O)
N21361557: C648.2 U59.4(LINE1L-)
N21391032: R417.2 U121.K5(RSTN)
N21391113: C269.1 C708.1 U121.C2(VDDI.1)
N21391608: C273.1 C290.1 R429.1 U121.E6(VFF.1) U121.F5(VFF.2) U121.J10(VFF.3) U121.K9(VFF.4)
N21411928: R332.2 R333.1 U3.24(MODE_SEL(VODSEL))
N21411951: R944.2 U132.28(PDN)
N21411993: R945.2 R946.2 U132.27(INTREQ/GPCL/VBLK)
N21412338: R947.2 U132.26(AVID)
N21412343: R950.2 U132.23(FIG/GLCO)
N21412499: C797.2 U132.2(AIP1B)
N21415881: C788.1 R952.2 R954.2
N21415900: C796.1 L25.2 R952.1
N21415906: C795.1 L24.1 R951.2 R953.2
N21415919: C715.1 L24.2 L25.1
N21553860: R937.1 R938.1 U122.4(TXD)
N21553866: R832.1 R935.1 R936.1 U122.2(EN)
N21553869: R831.2 R933.1 R934.1 R939.2 U122.1(RXD)
N21553972: D2.1(K) R830.1
N21553975: C716.1 D1.1(K) D2.2(A) U122.7(VSUP)
N21756433: R22.2 R838.1 R846.2 U3.31(INTB(BISTEN))
N21756809: R11.1 R841.2 U3.13(I2S_CLK/O8(CFG1))
N21756816: R9.1 R839.2 U3.12(I2S_WC/O7(CFG0))
N21756819: R10.1 R840.2 U3.11(I2S_DA/O6(RFB))
N21757005: C7.1 C719.1 R844.1 U3.17(CAPHS12(VDDHS))
N21757009: C13.1 C234.1 C718.1 R843.1 U3.7(CAPL12(VDDL))
N21757015: C8.1 C717.1 R842.1 U3.14(CAPP12(VDDP))
N21757246: C229.1 C231.1 L2.1 R845.1 U3.22(VDD33(VDDTX))
N21759370: R850.2 U123.7(CANH)
N21759373: R851.2 U123.6(CANL)
N21910555: C735.1 P5.4 R864.2
N21910572: P5.6 TP62.1
N21910578: P5.3 TP63.1
N21910586: P5.8 R865.2
N21910590: P5.7 R420.1
N21910592: P5.5 TP64.1
N22208304: P9.76 TP22.1(TP)
N22224993: P9.11 TP48.1(TP)
N22225609: P9.13 TP47.1(TP)
N22227190: P9.15 TP45.1(TP)
N22626207: R106.2 U129.4(Y)
N22626247: R100.1 U6.4(Y)
N22728109: P14.10(INSERT_COM) R?.1
N22765820: R583.2 R940.2 SW4.3(B) SW4.4(BB) U102.3(M\R\)
N22823202: R942.2 U54.6(CANL)
N22823205: R941.2 U54.7(CANH)
N22964373: J21.2 R83.2
N22964378: J24.2 R85.2
N24036072: C599.1 R684.2 R687.2
N24686365: R151.2 R152.1 U37.5(SENSE1)
N24686375: C329.1 U37.4(CT)
N24700289: R554.2 R555.2 U102.5(SENSE1)
N24700307: C421.1 U102.4(CT)
N25164864: C532.1 U56.7(SS)
N25164868: C515.2 R241.1 R244.2 U56.8(FB)
N25214719: R603.2 U50.7(VREF2) U50.8(EN)
N27151094: R269.1 U52.AF14(RTC_ISO)
N27840356: R301.1 U73.4(ACKN)
N27843210: R1.1 U73.3(ENN)
N28338968: R515.1 U41.14(2O\E\) U41.15(1O\E\)
N29597106: R577.2 R578.1 U105.1(A0)
N29597110: R575.2 R576.1 U105.2(A1)
N29597116: R573.2 R574.1 U105.3(NC)
N29675465: R625.1 R629.2 U117.4(ADD0)
N32582765: TP2.1 U73.1(VBUS_OUT.1) U73.2(VBUS_OUT.2)
N32742919: C235.1 C236.1 L3.2 U3.30(VDDIO)
N32835273: C232.1 U3.23(CMF(DE-EMPH))
N32916975: R20.2 R338.1 U3.6(IDX)
N33161549: C228.1 R8.2 U3.21(PDB)
N35662197: TP32.1 U45.N12(VPROG/TESTV)
N42624965: R211.2 R588.1 U45.E5(NSLEEP)
N43640412: R529.1 R531.2 U44.5(SENSE1)
N43640433: C348.1 U44.4(CT)
N45361223: Q3.4(G) R457.1
N45364158: Q4.4(G) R456.1
N46501256: C318.1 U92.6(CT)
N47347830: R709.2 U45.H8(I2C2_SDA_SDO)
N47347885: R708.2 U45.M3(I2C2_SCL_SCE)
N167456600: C307.1 R464.2
N167457561: C303.1 R461.2

Pads without a net: J17 6 10 11 14 18 20 22 24 26 28 30 32 34 36 38 40 42 44 46 48 50 52 54 55 56 59 60; NOREF 1; NOREF#5 1; NOREF#17 1; NOREF#26 1; NOREF#27 1; NOREF#31 1; NOREF#32 1; NOREF#33 1; NOREF#34 1; NOREF#35 1; NOREF#36 1; P9 10 17 21 23 25 27 29 35 36 38 39 40 41 43 44 45 46 57 59 61 62 65 67 69 71 74 75 78 79 80 81 82 84 85 86 88 90 91 93 94 96 98 99 100; P12 4; P14 11 12 13 14 15; U3 16; U18 4 5 6 11 12 13; U23 2 3 18 36 37; U35 4 10; U37 3; U41 10; U44 3; U45 B4 C9 K4 K5 K12 L4 M4 N3 N4; U46 16 17 21; U48 10; U52 A27 AC11 AD11 AE12 AF12 B28 Y10; U55 4; U56 3; U59 5 6 7 8 9 10 12 18 19 22 23 27 28 30 32 34 35; U65 J1 J9 L1 L9; U66 J1 J9 L1 L9; U67 A3 A7 F1 F9 H1 H9; U68 A3 A7 F1 F9 H1 H9; U69 A3 A7 F1 F9 H1 H9; U77 2; U78 2; U79 2; U100 1 3 4; U110 1; U115 A3 A7 F1 F9 H1 H9; U116 A3 A7 F1 F9 H1 H9; U117 3; U121 A1 A2 A6 A7 A8 A9 A10 A11 A12 A13 A14 B1 B7 B8 B9 B10 B11 B12 B13 B14 C1 C3 C5 C7 C8 C9 C10 C11 C12 C13 C14 D1 D2 D3 D4 D12 D13 D14 E1 E2 E3 E5 E8 E9 E10 E12 E13 E14 F1 F2 F3 F10 F12 F13 F14 G1 G2 G3 G10 G12 G13 G14 H1 H2 H3 H5 H12 H13 H14 J1 J2 J3 J5 J12 J13 J14 K1 K2 K3 K6 K7 K10 K12 K13 K14 L1 L2 L3 L12 L13 L14 M1 M2 M3 M7 M8 M9 M10 M11 M12 M13 M14 MA4 MA6 MA9 MA11 MAE1 MAE14 MAG2 MAG13 MAH4 MAH6 MAH9 MAH11 MB2 MB13 MD1 MD14 N1 N3 N5 N6 N8 N9 N10 N11 N12 N13 N14 P1 P2 P7 P8 P9 P10 P11 P12 P13 P14; U131 2 3; Y4 4 6

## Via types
v1: diameter 0.457, hole 0.254, TOP to BOTTOM, 903 vias
v2: diameter 0.508, hole 0.254, TOP to BOTTOM, 649 vias

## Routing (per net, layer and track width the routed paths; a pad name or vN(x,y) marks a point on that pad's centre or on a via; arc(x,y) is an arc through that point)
1V8_I2C1_SCL: length 1.8
  TOP w0.102: U45.L1 132.38,80.62 v1(132.78,81.02)
  BOTTOM w0.127: R708.1 133.39,81.63 v1(132.78,81.02)
1V8_I2C1_SDA: length 2.7
  TOP w0.102: v1(131.18,81.02) 131.58,80.62 U45.L2
  BOTTOM w0.127: R709.1 130.46,81.02 v1(131.18,81.02)
GND: length 921.9
  TOP w0.102: U52.AH8 v1(55.78,64.06)
  TOP w0.127: 61.13,59.26 U52.AA14 ; U52.H12 U52.J12 ; U52.AH28 v1(55.73,48.05) ; U52.V17 U52.U17
  TOP w0.152: U52.U21 U52.U20
  TOP w0.178: U52.K4 v1(71.12,66.89) U52.K5 ; v1(66.32,62.87) U52.T10 U52.T11 v1(65.55,61.22) U52.T12 ; U52.T15 U52.T14 v1(66.35,59.62) U52.R13 ; U52.T15 v1(65.54,58.09) U52.U15 U52.U14 ; U52.T15 U52.R15 ; U52.D19 v1(75.08,54.82) U52.E19 ; U52.J12 v1(71.15,60.45) ; U52.G8 v1(73.5,63.68) U52.G9 ; U52.AA14 v1(62.34,58.85) U52.AA15 ; U52.D13 v1(75.17,59.67) U52.E13 ; U52.N24 v1(67.95,50.82) U52.N25 ; U52.G7 v1(73.52,64.44) U52.F7 ; U52.AA8 v1(61.53,63.68) U52.AA9 62.05,63.13 62.05,62.58 U52.AA10 ; U52.V15 v1(63.94,58.85) U52.W15 ; U52.AE13 v1(59.09,60.44) U52.AD13 ; v1(48.58,26.49) 47.78,26.49 U66.J8 ; U52.N19 v1(68.76,54.88) U52.M19 ; 61.13,61.66 v1(61.54,62.08) U52.AA11 ; v1(65.54,56.49) U52.T17 v1(66.35,56.49) U52.T18 v1(65.54,56.49) ; v1(65.54,56.49) U52.U17 ; U52.AA20 v1(61.52,54.08) 61.13,54.45 ; U52.J15 v1(71.12,58.85) U52.K15 ; v1(35.88,26.49) 35.08,26.49 U65.J8 ; U52.AD24 v1(59.13,50.84) ; U52.AD10 v1(59.13,62.89) U52.AE10 ; v1(78.74,51.77) 78.74,51.8 78.49,52.05 U52.A23 ; 77.93,48.05 v1(78.51,47.98) ; U52.L14 v1(70.35,59.65) U52.L13 ; U52.K25 v1(70.35,50.82) U52.K24 ; U52.W24 v1(63.14,50.82) U52.W25 ; v1(67.18,61.25) U52.R12 ; U52.R21 v1(66.33,54.01) U52.T21 ; v1(67.94,58.07) U52.N15 v1(67.92,58.88) U52.N14 ; U52.U20 65.53,54.8
  TOP w0.203: U65.F9 v1(35.88,28.09) ; U52.AD19 v1(59.09,55.62) U52.AE19 ; U52.AH20 55.81,54.45 v2(55.75,54.51) ; v1(78.3,66.07) 77.99,65.71 U52.A6 ; 67.53,46.79 U52.P28 ; v1(63.53,47.32) U52.W28
  TOP w0.254: v1(128.78,74.62) 128.38,75.02 U45.D6 ; U66.D8 v1(46.98,30.5) ; v1(73.93,70.18) U52.F1 ; U65.D1 v1(28.68,29.7) U65.E1 ; C138.2 56.26,45.29 56.18,45.37 v2(56.18,45.39) ; C160.2 v1(76.78,31.57) ; v1(92.18,31.07) U69.A1 ; U68.A8 v1(84.23,30.27) ; v1(76.33,26.75) 76.2,26.88 C177.2 ; U45.B10 125.18,73.42 v1(124.78,73.02) ; v1(127.18,76.22) U45.F7 ; U45.E8 v1(127.18,75.42) U45.E7 ; C211.2 v2(38,17.17) ; U66.G9 v1(48.58,28.09) U66.F9 ; v1(127.18,77.02) U45.G7 ; v2(80.64,44.33) C657.2 80.64,46.38 v2(80.31,46.71) ; v1(60.65,23.85) U67.J9 ; U68.N9 84.64,21.06 v1(85.04,20.66) ; U65.D8 v1(34.28,30.5) ; U68.C9 v1(85.03,28.67) U68.D9 84.59,28.22 83.87,28.22 U68.D8 ; v1(77.83,31.07) U68.A1 ; C161.2 90.45,32.26 v1(90.91,31.8) ; v1(99.39,22.26) 98.99,22.66 U69.L9 ; v1(131.99,73.02) 131.58,73.42 U45.B2 ; v1(41.38,27.29) U66.G1 ; 80.85,47.7 80.09,47.7 v2(79.91,47.53) ; v1(35.88,32.1) U65.B9 ; U45.G4 129.98,77.42 v1(130.39,77.02) U45.F4 ; U66.E8 v1(47.78,29.7) ; C182.2 38.13,24.89 v2(38.05,24.97) ; C184.2 74.5,24.08 v2(74.24,24.34) ; C557.2 v2(49.23,43.69) ; U67.L1 v1(53.45,22.25) ; U66.D1 v1(41.38,29.7) U66.E1 ; U67.J1 v1(53.45,23.85) ; v1(128.78,76.22) 128.38,76.62 U45.F6 ; U69.D1 v1(92.98,28.67) ; U67.F2 v1(55.05,27.07) ; v1(124.78,77.02) U45.G10 ; U68.J9 84.64,24.26 v1(85.04,23.86) ; v1(127.18,74.62) U45.D7 ; C200.2 93.22,17.86 v2(93.75,18.39) ; v1(86.56,29.29) 86.64,29.21 C171.2 v2(88.57,29.21) ; v1(131.99,73.82) 131.58,74.22 U45.C2 ; U69.B8 v1(98.58,29.47) ; U45.D4 v1(129.59,74.62) U45.D5 ; v2(85.75,17.78) C195.2 ; C170.2 90.73,30.81 v1(90.96,31.04) ; v1(131.98,82.62) U45.N2 ; U45.J4 129.98,79.02 v1(130.38,79.42) ; U52.A1 v1(78.28,70.11) ; U45.H7 v1(127.98,78.62) 128.38,79.02 U45.J6 ; U45.M12 v1(123.18,81.82) U45.M13 ; U67.B2 v1(54.25,30.27) ; U52.B1 v1(77.24,70.23) ; U45.A4 129.98,72.62 v1(130.39,73.02) ; v1(42.18,29.7) U66.E2 ; U67.A1 v1(53.45,31.07) ; v2(40.64,17.17) C212.2 ; U67.D8 v1(59.85,28.67) U67.D9 ; v1(99.39,20.66) 98.99,21.06 U69.N9 ; v1(124.78,81.02) 125.18,80.62 U45.L10 ; U66.A9 v1(48.58,32.9) ; U69.D8 U69.D9 v1(99.39,28.67) U69.C9 ; C137.2 v2(53.04,47.93) ; v1(30.28,32.1) U65.B3 ; v1(130.38,80.22) U45.K3 ; U65.P9 35.48,22.09 v1(35.88,22.49) ; U65.M9 v1(35.88,24.09) ; v2(52.7,17.3) C214.2 ; v1(129.59,77.02) U45.G5 ; U45.J9 125.98,79.02 v1(125.58,79.42) 125.18,79.02 U45.J10 ; U69.J1 92.58,24.26 v1(92.18,23.86) ; v1(35.88,28.09) U65.G9 ; U67.A8 v1(59.85,31.07) ; v1(122.38,82.62) U45.N13 ; v1(28.68,27.29) U65.G1 ; U45.L7 127.58,80.62 v1(127.18,81.02) ; v1(123.98,73.02) 124.38,73.42 U45.B11 ; v1(77.83,23.86) 78.23,24.26 U68.J1 ; U68.L1 v1(78.64,23.06) ; U45.A7 127.58,72.62 v1(127.18,72.22) ; U68.F2 78.63,27.07 v1(77.79,27.07) ; v1(41.38,32.1) U66.B1 ; v1(63.61,70.41) 63.6,70.25 63.55,70.2 63.55,69.84 U52.W1 ; v2(83.52,48.83) C556.2 ; U68.D1 v1(78.63,28.67) ; U66.P1 v1(41.06,22.09) ; U69.B2 93.38,29.87 v1(92.98,30.27) 92.58,29.87 U69.B1 ; U69.A8 v1(98.58,30.27) ; U65.G8 v1(34.28,28.09) ; v1(132.78,82.62) U45.N1 ; v1(100.71,22.25) 100.76,22.3 C190.2 ; v1(28.68,20.09) U65.T1 ; U69.L1 v1(92.99,23.06) ; U69.F2 93.38,26.66 v1(92.98,27.07) ; v1(131.19,73.82) U45.C3 ; v1(124.78,76.22) U45.F10 ; C210.2 v2(27.94,17.3) ; v1(42.98,32.1) U66.B3 ; U67.C9 v1(60.65,29.47) ; v1(129.58,81.02) 129.18,80.62 U45.L5 ; U52.A2 v1(78.54,68.81) ; U66.J2 v1(42.98,25.69) ; C193.2 38.13,19.2 v2(38.05,19.13) ; U66.T9 v1(48.58,20.09) ; U52.AH1 v1(56.41,70.18) ; v1(41.38,20.09) U66.T1 ; v1(125.58,76.22) U45.F9 ; v1(59.53,70.62) U52.AD1 ; U67.N1 v1(53.45,20.65) ; U68.F8 83.83,26.66 v1(84.23,27.07) ; U68.L9 84.64,22.66 v1(85.04,22.26) ; U45.F5 v1(129.59,76.22) 129.98,75.82 U45.E4 ; v1(92.18,20.66) 92.58,21.06 U69.N1 ; v1(132.78,72.22) 132.38,72.62 U45.A1 ; U66.P9 48.18,22.09 v1(48.58,22.49) ; v1(122.38,72.22) U45.A13 ; v1(124.78,75.42) U45.E10 ; U67.D1 v1(53.45,28.67) ; C178.2 89.59,26.98 v2(88.72,26.98) ; U45.L6 128.38,80.62 v1(127.98,81.02) ; U68.B8 v1(84.23,29.47) ; U52.AH2 v1(55.8,68.96) ; v2(87.71,43.44) C562.2 v2(87.71,46.13) ; v2(86.64,48.67) C589.2 ; U45.M1 v1(131.98,81.82) U45.M2 ; U68.B1 78.23,29.87 v1(78.63,30.27) 79.03,29.87 U68.B2 ; U66.G8 v1(46.98,28.09) ; v1(41.38,24.09) U66.M1 ; v2(99.95,17.76) 99.95,18.75 C196.2 ; U65.B1 28.68,32.1 v1(28.57,32.1) ; C656.2 v2(79.65,44.91) ; U65.P1 v1(28.45,22.09) ; v1(125.58,75.42) U45.E9 ; U69.J9 98.99,24.26 v1(99.39,23.86) ; v2(73,42.62) C548.2 ; v1(130.38,78.62) U45.H4 ; U52.AG1 v1(57.18,70.26) ; C213.2 v2(50.24,17.12) ; v1(29.48,29.7) U65.E2 ; C559.2 v2(79.22,46.31) ; U65.A9 v1(35.08,32.9) ; v1(129.58,78.62) U45.H5 ; v1(28.68,24.09) U65.M1 ; U67.B8 v1(59.85,30.27) ; U45.L9 v1(126.38,80.22) 126.78,80.62 U45.L8 ; v1(48.58,32.1) U66.B9 ; C158.2 v2(85.7,33.86) ; U68.N1 78.23,21.06 v1(77.83,20.66) ; U67.F8 v1(59.05,27.07) ; U52.R1 v1(66.73,70.28) ; U69.F8 98.18,26.66 v1(98.58,27.07) ; v1(128.78,78.62) U45.H6 ; C199.2 v2(79.43,17.99) ; v1(123.18,73.82) U45.C12 ; C185.2 v2(88.72,23.83) ; C169.2 v1(76.4,30.56) ; v1(124.78,74.62) U45.D10 ; U65.J2 v1(30.28,25.69) ; R289.2 v1(100.99,26.49) ; U52.A14 v2(79.2,59.26) ; 71.53,48.05 71.53,47.38 v1(71.53,47.37) ; v1(124.78,78.62) U45.H10 ; U65.E8 v1(35.08,29.7) ; U65.T9 v1(35.88,20.09) ; U66.M9 v1(48.58,24.09) ; v1(60.65,20.65) U67.N9 ; v1(59.85,23.05) U67.L9 ; U67.B1 v1(53.45,30.27) ; v1(70.79,70.28) U52.K1
  TOP w0.305: C143.2 v2(51.26,53.57) ; C584.2 70.98,45.16 v2(70.98,45.16) ; v2(49.23,65.34) C108.1 v2(49.23,67.4) ; 67.53,46.79 67.53,45.57 v2(67.36,45.39) ; C148.2 53.62,45.93 v2(53.26,46.28) ; C183.2 v2(50.83,24.97) ; v2(57.18,79.15) C357.2 v2(57.18,76.71) ; v2(102.84,33.1) C163.2 v2(100.76,33.1) ; v2(81.61,68.04) v2(81.61,66.49) ; v2(67.84,74.81) C487.1 v2(67.84,77.24) ; v2(48.59,61.88) C382.2 v2(51.13,61.88) ; C431.2 v2(127.71,67.01) ; C631.2 v2(69.24,29.57) ; v2(48.64,71.4) C406.2 v2(51.08,71.4) ; v2(73.18,77.24) C453.1 v2(73.18,74.81) ; v2(91.59,66.88) C356.2 v2(88.9,66.88) ; v2(55.44,75.9) C111.1 v2(57.51,75.9) ; v2(75.76,75.9) C374.1 v2(77.81,75.9) ; v2(83.39,51.88) C389.2 v2(83.39,53.43) ; v2(81.61,58.38) v2(81.61,56.84) ; v2(39.24,26.58) C366.2 v2(39.24,28.23) ; v2(87.91,69.12) C360.1 v2(87.91,66.68) ; v2(84.65,52.53) C367.1 v2(86.7,52.53) ; R288.2 v1(86.33,26.49) ; v2(81.6,75.9) C90.1 v2(83.67,75.9) ; v2(99.16,34.78) 99.16,34.72 99.26,34.62 99.26,33.48 ; C147.2 v2(67.59,41.07) ; C189.2 v1(86.56,21.92) ; C162.2 v2(88.6,32.34) ; C139.2 v2(62.41,45.16) ; v2(84.4,69.05) C105.1 v2(84.4,67) ; C194.2 v2(50.83,19.15) ; v2(81.61,53.43) v2(81.61,51.88) ; v2(90.51,56.97) C96.1 v2(88.46,56.97) ; v1(100.84,29.67) C172.2 v2(102.77,29.67) ; v2(85.41,56.97) C93.1 v2(87.46,56.97) ; C136.2 v2(63.32,41.72)
  TOP w0.381: C99.1 v2(125.55,67.01) ; C433.2 v2(124.41,67.01)
  BOTTOM w0.102: C391.1 69.29,56.33 ; C391.1 68.8,55.83 ; C391.1 69.29,55.34 ; C391.1 69.79,55.83 ; U68.B8 83.83,30.21 ; U68.B8 83.48,29.86 ; U68.B8 84.18,29.86 ; U68.B8 83.83,29.51 ; 78.44,58 C504.2 ; C504.2 79.06,58.75 ; C504.2 77.81,58.75 ; C504.2 78.44,59.5 ; 67.07,57.38 C507.1 ; C507.1 68.06,57.38 ; C507.1 67.56,56.89 ; 84.28,22.66 U68.L9 ; U68.L9 84.98,22.66 ; U68.L9 84.63,23.01 ; U68.L9 84.63,22.31 ; U116.C9 78.23,29.41 ; U116.C9 78.58,29.06 ; U116.C9 78.23,28.71 ; U116.C9 77.88,29.06 ; C475.2 65.19,63.43 ; C475.2 64.7,63.93 ; C475.2 64.7,62.93 ; U116.A1 84.63,31.01 ; U116.A1 84.98,30.66 ; U116.A1 84.28,30.66 ; U116.A1 84.63,30.31 ; 72.48,58.75 C502.2 ; C502.2 72.97,59.25 ; C502.2 73.47,58.75 ; 90.64,32.72 C585.2 91.26,31.97 ; 77.88,22.66 U68.L1 ; U68.L1 78.23,23.01 ; U68.L1 78.23,22.31 ; 98.98,22.31 U69.L9 ; U69.L9 98.63,22.66 ; U69.L9 99.33,22.66 ; U69.L9 98.98,23.01 ; 84.73,34.48 C158.2 83.98,33.86 ; 89.69,29.66 C615.2 88.94,29.03 ; 57.1,60.54 C501.2 ; C501.2 56.48,61.29 ; C501.2 57.1,62.04 ; C501.2 57.72,61.29 ; 55.14,62.45 C480.2 ; C480.2 55.89,63.07 ; C480.2 54.39,63.07 ; 59.14,63.58 C399.1 ; C399.1 59.64,64.07 ; C399.1 60.13,63.58 ; 87.53,32.96 C162.2 86.78,32.34 ; U68.N9 84.63,21.41 ; U68.N9 84.28,21.06 ; U68.N9 84.63,20.71 ; U68.N9 84.98,21.06 ; C606.2 40.59,30.42 ; C606.2 41.09,29.92 ; C606.2 40.09,29.92 ; 74.59,20.14 C645.2 75.34,19.52 ; 71.77,70.19 C481.2 71.77,71.44 ; R565.2 125.87,73.07 ; R565.2 125.5,72.65 ; R565.2 125.13,73.07 ; 93.03,29.86 U69.B2 93.38,29.51 ; 126.44,71.97 C680.2 ; C680.2 125.95,72.47 ; C680.2 126.94,72.47 ; 63.48,58.14 C466.2 63.98,57.64 ; 34.95,28.49 C611.2 34.45,28.98 ; 76.48,51.58 C541.2 76.97,52.07 ; 40.78,22.18 C639.2 39.79,22.18 ; 98.63,21.06 U69.N9 ; U69.N9 98.98,20.71 ; U69.N9 99.33,21.06 ; U69.N9 98.98,21.41 ; 46,25.47 R691.2 45.5,24.97 ; 75.51,69.69 C437.1 ; C437.1 76.01,70.18 ; C437.1 75.02,70.18 ; C437.1 75.51,70.68 ; U115.C9 92.93,29.06 ; U115.C9 92.58,28.71 ; U115.C9 92.23,29.06 ; 99.33,24.26 U69.J9 98.98,23.91 ; 89.69,19.52 C644.2 88.94,20.14 ; U68.D9 84.98,28.26 ; U68.D9 84.28,28.26 ; U68.D9 84.63,28.61 ; U68.D9 84.63,27.91 ; C482.2 76.77,61.42 ; C482.2 75.78,61.42 ; C482.2 76.28,60.92 ; 121.21,82.9 C346.1 ; C346.1 122.02,82.1 ; C346.1 122.02,82.9 ; C346.1 121.21,82.1 ; 75.16,22.7 R695.2 ; R695.2 74.66,23.19 ; R695.2 75.65,23.19 ; 98.53,29.86 U69.B8 98.18,30.21 ; 77.55,67.4 C455.1 ; C455.1 77.55,68.39 ; C455.1 77.05,67.9 ; C455.1 78.04,67.9 ; C528.2 74.11,53.93 ; C528.2 73.11,53.93 ; C528.2 73.61,54.42 ; 68.68,58.53 C495.2 ; C495.2 68.68,59.52 ; C495.2 69.17,59.03 ; 76.09,32.08 C596.2 75.34,32.71 ; R537.2 128.21,76.44 ; R537.2 127.84,76.03 ; R537.2 127.47,76.44 ; 77.3,63.58 C462.2 ; C462.2 78.55,63.58 ; C462.2 77.93,62.83 ; C462.2 77.93,64.33 ; 88.28,22.81 C637.2 87.53,22.19 ; U116.B1 84.63,30.21 ; U116.B1 84.98,29.86 ; U116.B1 84.28,29.86 ; U116.B1 84.63,29.51 ; U116.A8 79.03,31.01 ; U116.A8 79.03,30.31 ; U116.A8 78.68,30.66 ; 65.11,57.23 C508.2 65.61,57.72 ; 73.88,68.66 C444.1 ; C444.1 74.37,68.16 ; C444.1 74.37,69.15 ; 79.03,27.01 U68.F2 78.68,26.66 ; 92.58,22.31 U69.L1 ; U69.L1 92.58,23.01 ; U69.L1 92.23,22.66 ; C506.2 57.72,58.88 ; C506.2 57.1,58.13 ; C506.2 57.1,59.63 ; C506.2 56.48,58.88 ; 70.85,55.76 C385.2 ; C385.2 71.84,55.76 ; C385.2 71.35,55.26 ; C443.2 64.59,68.52 ; C443.2 65.09,68.02 ; C443.2 64.59,67.53 ; 47.02,29.28 C612.2 47.51,28.78 ; 69.65,60.9 C390.1 69.15,61.4 ; 83.48,26.66 U68.F8 ; U68.F8 84.18,26.66 ; U68.F8 83.83,27.01 ; 61.37,28.92 61.37,29.42 61.86,29.42 ; 98.63,30.66 U115.A1 ; U115.A1 98.98,30.31 ; U115.A1 99.33,30.66 ; 40.67,31.46 C587.2 ; C587.2 41.16,31.96 ; C587.2 40.17,31.96 ; 124.83,77.56 R535.2 ; R535.2 124.42,77.93 ; R535.2 124.83,78.3 ; 88.28,26.88 C629.2 87.53,27.5 ; 129.86,72.98 C100.1 129.36,72.48 ; 69.3,62.18 C363.1 70.3,62.18 ; 69.23,70.19 C477.2 68.48,70.82 ; 50.37,30.17 C610.2 50.37,29.17 ; 79.03,29.51 U68.B2 78.68,29.86 ; 66.5,60.03 C485.2 66,60.53 ; 42.06,29.94 C600.2 41.57,30.43 ; 74.24,65.66 C458.1 74.74,65.17 ; U69.F8 98.18,27.01 ; U69.F8 97.83,26.66 ; U69.F8 98.53,26.66 ; 75.34,29.66 C616.2 74.59,29.03 ; 84.63,23.91 U68.J9 84.98,24.26 ; 65.61,61.43 C461.1 ; C461.1 65.61,62.42 ; C461.1 65.11,61.93 ; 93.38,28.61 U115.D8 93.03,28.26 ; 61.3,24.56 R693.2 60.81,24.07 ; 130.4,76.55 C408.1 129.91,76.05 ; 76.28,55.97 C500.2 ; C500.2 75.78,56.47 ; C500.2 76.77,56.47 ; C500.2 76.28,56.96 ; C603.2 53.23,30.43 ; C603.2 52.23,30.43 ; C603.2 52.73,30.93 ; 65.87,54.82 66.37,54.82 ; 66.37,54.82 66.87,54.82 ; 66.37,54.82 66.37,54.32 ; 66.37,54.82 66.37,55.31 ; 98.98,29.51 U115.B1 ; U115.B1 99.33,29.86 ; U115.B1 98.98,30.21 ; U115.B1 98.63,29.86 ; 64.33,55.58 C498.1 63.33,55.58 ; 93.03,30.66 U115.A8 93.38,30.31 ; 61.49,27.83 C614.2 61.49,28.82 ; C403.1 134.05,72.09 ; C403.1 133.06,72.09 ; C403.1 133.15,71.69 ; C403.1 133.55,71.59 ; 102.63,22.81 C636.2 101.88,22.19 ; 78.23,28.61 U68.D1 78.58,28.26 ; 70.31,58.51 C384.2 70.8,59.01 ; 127.97,76.01 C381.1 127.47,75.52 ; 89.01,23.19 R694.2 89.51,22.7 ; C400.1 59.64,66.49 ; C400.1 59.14,65.99 ; C400.1 60.13,65.99 ; 56.22,67.9 C454.2 56.72,68.39 ; 68.02,62.42 C386.1 67.53,61.93 ; C449.2 62.31,68.27 ; C449.2 62.31,67.27 ; C449.2 62.8,67.77 ; C622.2 37.1,28.15 ; C622.2 36.11,28.15 ; C622.2 36.6,28.64 ; U69.N1 92.58,21.41 ; U69.N1 92.58,20.71 ; U69.N1 92.93,21.06 ; U69.N1 92.23,21.06 ; 78.23,20.71 U68.N1 ; U68.N1 77.88,21.06 ; U68.N1 78.23,21.41 ; U68.N1 78.58,21.06 ; C542.1 78.44,51.37 ; C542.1 77.94,50.88 ; C542.1 78.93,50.88 ; 67.01,68.9 C442.2 67.01,67.91 ; 67.53,55.07 68.02,55.07 68.02,54.57 ; 55.14,63.71 55.12,63.73 ; 48.81,28.15 C621.2 49.8,28.15 ; 90.44,32.08 C595.2 89.69,32.71 ; 125.39,79.45 C352.2 124.89,78.96 ; 68.45,70.82 C468.2 67.7,70.19 ; 28.33,31.96 C588.2 27.84,31.46 ; 102.63,26.88 C628.2 101.88,27.5
  BOTTOM w0.203: 74.75,52.05 C537.2 75.59,52.05 ; U69.L9 v1(99.39,22.26) ; U69.N1 v1(92.18,20.66) ; U68.N1 v1(77.83,20.66) ; U115.A8 v1(92.98,30.27) 93.38,29.87 U69.B2 ; U69.D9 v1(99.39,28.67) ; v1(92.99,23.06) 92.59,22.66 U69.L1 ; v1(73.5,63.68) 73.47,63.64 72.85,63.64 ; v1(77.79,27.07) 78.63,27.07 U68.F2 ; v1(92.98,27.07) 93.38,26.66 U69.F2 ; v1(78.63,28.67) U116.C9 ; v1(78.63,28.67) U68.D1 ; v1(78.63,28.67) 79.03,28.27 U116.D8 ; 66.37,54.82 66.33,54.78 v1(66.33,54.01) ; U68.L9 v1(85.04,22.26) ; v1(77.83,23.86) 78.23,24.26 U68.J1 ; C467.2 62.71,61.67 ; v1(68.76,54.88) 68.57,55.07 68.02,55.07 ; C466.2 63.98,58.53 63.97,58.55 63.97,58.82 v1(63.94,58.85) ; v1(92.18,23.86) 92.58,24.26 U69.J1 ; 69.82,55.35 C574.2 70.71,54.51 ; U68.J9 v1(85.04,23.86) ; v1(84.23,30.27) U68.B8 ; v1(84.23,30.27) U116.A1 ; v1(84.23,30.27) U116.B1 ; U68.F8 v1(84.23,27.07) ; U69.J9 v1(99.39,23.86) ; C497.2 65.48,58.15 v1(65.54,58.09) ; C508.2 65.61,56.55 v1(65.54,56.49) ; 65.53,54.8 64.85,54.12 C530.2 ; 65.15,66.55 64.72,66.25 64.24,66.47 ; C384.2 70.31,59.61 v1(70.35,59.65) ; C399.1 59.13,63.07 v1(59.13,62.89) ; U68.D9 v1(85.03,28.67) ; v1(99.39,20.66) U69.N9 ; C457.2 66.58,66.37 66.51,66.44 66.45,66.44 66.45,66.45 ; v1(67.92,58.88) 68.07,59.03 C495.2 ; 68.58,59.87 C491.2 67.84,60.58 ; C507.1 67.56,57.69 v1(67.94,58.07) ; U115.A1 v1(98.58,30.27) U115.B1 ; 58.04,66.35 C464.2 57.18,65.66 ; U116.A8 v1(78.63,30.27) 79.03,29.87 U68.B2 ; 73.18,55.25 72.74,55.73 72.09,55.73 ; U68.L1 78.24,22.66 v1(78.64,23.06) ; v1(85.04,20.66) U68.N9 ; 69.39,68.28 69.39,67.82 ; U69.F8 v1(98.58,27.07) ; C526.2 77.14,53.52 ; C112.2 60.15,59.16 ; U69.B8 v1(98.58,29.47) ; C518.1 63.22,58.07
  BOTTOM w0.254: C158.2 v2(85.7,33.86) ; C609.2 54.25,29.55 v1(54.25,30.27) ; C667.2 v2(97.03,13.71) ; v1(35.88,32.1) 36.15,31.83 C598.2 ; v2(72.86,14.48) C630.2 v2(70.8,14.48) ; 61.37,29.42 60.7,29.42 v1(60.65,29.47) ; C160.2 v1(76.78,31.57) ; C668.2 v2(95.5,13.71) ; C672.2 v2(88.04,13.68) ; v1(28.57,32.1) 27.98,32.1 C588.2 ; C625.2 52.48,27.13 v1(52.1,27.51) ; v1(41.06,22.09) 40.37,22.09 C639.2 ; v2(85.75,17.78) C650.2 ; 70.18,70.82 C477.2 69.23,71.57 69.22,71.58 ; U115.D8 92.98,28.66 v1(92.98,28.67) ; 66.68,70.82 C468.2 67.7,71.57 67.69,71.58 ; 131.14,83.39 131.14,82.67 131.18,82.62 ; v2(50.83,24.97) 52.12,24.97 C633.2 ; v1(30.28,32.1) 30.51,32.32 C583.2 ; v1(90.91,31.8) 90.87,31.84 90.87,32.32 C585.2 ; C623.2 46.98,27.42 v1(46.98,28.09) 46.98,28.75 C612.2 ; v2(90.93,16.03) C670.2 v2(90.93,13.59) ; C569.2 v2(51.59,40.29) ; C608.2 57.76,29.54 v1(57.59,29.38) ; v1(92.98,28.67) 92.98,28.67 U115.C9 ; v1(92.98,28.67) 92.58,28.27 U69.D1 ; v1(62.43,25.4) 62.2,25.63 C632.2 ; C484.2 74.27,61.29 v1(74.32,61.24) ; v1(90.93,23.19) R694.2 ; C587.2 40.81,32.1 v1(41.38,32.1) ; C614.2 61.93,28.32 v1(62.26,28.65) ; v1(41.38,29.7) 40.82,29.7 C606.2 ; 46.07,52.78 v2(45.42,52.12) ; C616.2 75.79,29.03 v1(76.3,29.54) ; R691.2 v1(46.18,25.69) ; v1(71.15,60.45) 71.17,60.48 C469.2 ; v2(51.26,53.57) 51.87,54.18 C519.2 ; v2(75.44,13.59) C678.2 v2(75.44,16.03) ; v1(100.79,23.01) 100.99,22.81 C636.2 ; C595.2 88.85,32.08 v2(88.6,32.34) C162.2 ; v2(50.9,21.64) 51,21.54 C641.2 ; v1(35.88,28.09) 36.55,28.09 C622.2 ; v1(67.18,61.25) 66.5,60.57 C485.2 ; C541.2 77.51,51.58 v1(77.57,51.64) ; C603.2 52.9,30.27 v1(53.45,30.27) ; v2(53.39,58.78) C512.2 54.25,58.91 54.85,59.5 54.97,59.59 56.08,59.59 ; 129.62,82.76 130.38,82.62 ; C624.2 34.28,27.42 v1(34.28,28.09) ; C572.2 77.44,39.42 77.47,39.42 77.47,39.41 v2(77.48,39.41) ; C590.2 59.84,31.07 v1(59.85,31.07) ; C581.2 99.16,33.94 v2(99.16,34.78) ; C591.2 53.45,31.75 v1(53.45,31.07) ; C610.2 v2(51.08,29.67) ; v1(65.55,61.22) 65.48,61.29 C489.2 ; C621.2 49.25,28.09 v1(48.58,28.09) ; v2(88.72,26.98) 87.63,26.98 C629.2 ; C528.2 v1(74.35,54.07) ; v1(35.08,29.7) 34.95,29.56 C611.2 ; R692.2 v1(33.48,25.69) ; 72.72,70.82 C481.2 70.76,70.82 ; C615.2 v1(91.01,29.03) ; v2(101.76,13.59) 101.75,13.6 C665.2 v2(101.75,16.03) ; v1(48.58,32.1) 48.85,31.83 C597.2 ; C679.2 v2(74.02,13.69) ; v2(61.24,41.07) C564.2 ; C571.2 v2(59.13,39.56) ; C640.2 62.51,21.54 v1(63.09,21.54) ; C674.2 v2(83.52,13.71) ; v1(70.43,62.05) 69.93,62.05 C363.1 ; C644.2 v1(90.75,20.14) ; C480.2 55.14,63.71 55.45,63.99 55.71,63.99 v1(55.78,64.06) ; C549.2 60.85,54.08 v1(61.52,54.08) ; C666.2 v2(98.55,13.71) ; v1(34.28,30.5) 34.28,31 34.09,31.19 C594.2 ; C570.2 49.2,41.46 v2(49.2,40.69) ; C671.2 v2(89.56,13.68) ; C580.2 48.58,33.52 v1(48.58,32.9) ; C600.2 42.18,30.31 v1(42.18,29.7) ; R693.2 v1(60.65,23.85) ; v1(86.49,22.81) C637.2 ; C613.2 32.11,26.62 v1(32.41,26.93) ; v1(28.68,29.7) 28.56,29.82 C605.2 ; C677.2 v2(78.82,13.71) ; C675.2 v2(81.99,13.71) ; C649.2 99.95,18.82 v2(99.95,17.76) ; C676.2 v2(80.34,13.71) ; C669.2 v2(94.11,13.71) ; C486.2 60.66,61.19 v1(61.54,62.08) ; C645.2 v1(76.28,20.14) ; C664.2 v2(104.1,14.05) ; v2(86.77,13.59) C673.2 v2(86.77,16.03) ; C458.1 v1(73.52,64.44) ; C506.2 56.13,59.57
  BOTTOM w0.305: 17.86,82.18 C344.2 ; C344.2 18.43,82.76 ; C344.2 17.86,83.33 ; 102.31,39.26 C573.2 ; C573.2 102.31,40.4 ; C573.2 102.88,39.83 ; 102.44,159.91 C235.2 ; C235.2 101.74,160.73 ; C235.2 102.44,161.56 ; v2(81.61,70.5) v2(81.61,68.85) ; 13.98,87.96 C335.2 ; C335.2 14.55,87.39 ; C335.2 15.13,87.96 ; C295.1 156.03,122.96 ; C295.1 154,122.96 ; C295.1 155.02,123.66 ; 42.18,69.67 C429.2 42.88,68.85 ; 58.23,78.06 C460.2 ; C460.2 59.63,78.06 ; C460.2 v2(58.93,79.28) ; C460.2 v2(58.93,76.84) ; v2(84.4,63.81) C465.1 v2(84.4,65.89) ; U100.20 10.17,78.38 ; U100.20 9.73,77.23 ; U100.20 9.73,79.52 ; 119.58,131.21 C280.2 ; C280.2 120.16,131.78 ; C280.2 119.01,131.78 ; 112.09,159.91 C234.2 ; C234.2 111.39,160.73 ; C234.2 112.09,161.56 ; v2(52.65,70.04) v2(52.65,71.59) ; C522.2 45.42,55.77 ; C522.2 45.42,54.62 ; C522.2 44.84,55.2 ; 42.88,78.15 C358.2 ; C358.2 43.45,78.72 ; C358.2 42.88,79.29 ; 107.26,159.91 C236.2 ; C236.2 107.26,161.05 ; C236.2 107.84,160.48 ; C233.2 143.21,160.66 ; C233.2 141.17,160.66 ; C233.2 142.19,159.96 ; C540.2 15.25,51.51 ; C540.2 14.68,50.94 ; C540.2 14.11,51.51 ; 152.29,52.66 R643.2 ; R643.2 152.86,53.23 ; R643.2 153.43,52.66 ; C525.2 21.29,55.01 ; C525.2 21.29,53.86 ; C525.2 21.86,54.43 ; v2(58.36,75.9) C483.1 v2(60.41,75.9) ; R473.2 123.08,108.41 ; R473.2 121.93,108.41 ; R473.2 122.5,108.98 ; 28.07,16.91 C619.2 27.37,16.08 ; R615.2 16.33,58.82 ; R615.2 15.76,58.24 ; R615.2 16.9,58.24 ; U123.2 124.73,158.96 ; U123.2 124.16,157.75 ; U123.2 124.16,160.16 ; U123.2 123.58,158.96 ; 21.98,84.03 C340.2 ; C340.2 23.64,84.03 ; C340.2 22.81,84.72 ; 159.21,110.76 R461.1 159.78,111.33 ; 123.13,100.84 U92.5 123.52,101.35 ; 124.19,85.23 R483.2 124.19,84.34 ; 143.71,109.36 C309.1 144.29,109.93 ; 13.67,53.61 C527.2 ; C527.2 13.67,54.75 ; C527.2 13.09,54.18 ; 120.16,133.94 C274.2 119.01,133.94 ; C638.2 26.7,22.94 v2(26.01,22.94) ; 162.83,64.89 U105.4 ; U105.4 163.4,63.36 ; U105.4 163.4,66.41 ; U105.4 163.97,64.89 ; 4.58,62.05 C472.2 ; C472.2 5.73,62.05 ; C472.2 5.16,61.48 ; C472.2 4.7,61.6 ; v2(55.69,73.23) C89.2 v2(57.24,73.23) ; 23.83,88.03 R481.1 ; R481.1 24.4,88.6 ; R481.1 23.83,89.17 ; U79.4 131.64,158.27 ; U79.4 131.23,157.51 ; U79.4 132.05,157.51 ; U79.4 131.64,156.75 ; v2(81.61,65.67) v2(81.61,64.02) ; C607.1 7.06,29.86 ; C607.1 6.49,29.29 ; C607.1 7.06,28.72 ; C529.2 54.01,45.54 v2(53.26,46.28) ; 33.03,53 R636.2 33.48,53.49 ; R532.1 24.4,79.96 ; R532.1 23.83,79.39 ; R532.1 23.83,80.53 ; 15.32,73.93 C405.2 15.32,75.07 ; R617.2 10.18,58.06 ; R617.2 9.27,57.15 ; R617.2 9.27,58.06 ; R617.2 10.18,57.15 ; 37.6,56.47 R620.2 ; R620.2 38.09,56.02 ; R620.2 38.09,56.91 ; 8.43,79.52 U100.18 8.43,77.23 ; v2(70.18,73.74) C456.1 v2(72.22,73.74) ; C546.2 2.24,52.34 ; C546.2 3.06,51.64 ; C546.2 1.41,51.64 ; 39.83,70.37 C423.2 ; C423.2 39.26,70.94 ; C423.2 39.83,71.52 ; U110.3 13.39,56.86 ; U110.3 12.8,57.35 ; U110.3 12.22,56.86 ; 124.92,135.02 C273.2 124.92,133.87 ; C411.2 15.13,72.34 ; C411.2 13.98,72.34 ; C411.2 14.55,71.77 ; 167.14,68.4 R569.1 ; R569.1 167.63,67.96 ; R569.1 167.63,68.85 ; 14.11,85.04 R515.2 ; R515.2 14.68,85.61 ; R515.2 15.25,85.04 ; 46.11,61.93 C110.2 ; C110.2 46.69,62.5 ; C110.2 46.69,61.36 ; 109.04,71.52 R555.1 109.61,70.94 ; 52.79,31.83 C591.2 ; C591.2 53.37,31.26 ; C591.2 53.37,32.4 ; 136.09,78.95 136.04,79 C353.1 136.09,80.09 136.86,80.85 ; 35.95,70.94 C424.2 ; C424.2 36.53,70.37 ; C424.2 36.53,71.52 ; 43.57,82.37 C348.2 43,82.95 ; 106.3,163.47 R333.2 ; R333.2 107.21,162.56 ; R333.2 106.3,162.56 ; C342.1 120.65,85.04 ; C342.1 120.65,83.01 ; C342.1 119.95,84.03 ; 124.85,63.89 R592.2 123.96,63.89 ; 78.78,53.98 C509.2 79.48,54.8 ; C433.2 124.98,67.9 ; C433.2 124.41,67.32 ; C433.2 123.84,67.9 ; v2(88.46,63.58) C94.1 v2(90.51,63.58) ; R642.2 155.97,52.66 ; R642.2 154.83,52.66 ; R642.2 155.4,53.23 ; 3.45,78.38 U100.11 ; U100.11 3.88,79.52 ; U100.11 3.88,77.23 ; 136.22,78.13 C375.1 134.19,78.13 ; v2(52.65,66.82) v2(52.65,65.17) ; v2(52.65,60.34) v2(52.65,61.99) ; 149.75,52.66 R644.2 ; R644.2 150.32,53.23 ; R644.2 150.89,52.66 ; v2(83.39,55.9) C392.1 v2(83.39,54.24) ; 45.8,59.83 C117.2 ; C117.2 45.8,60.98 ; C117.2 45.22,60.4 ; 150.63,121.11 R455.1 151.21,121.68 ; C521.2 48.56,55.1 v2(48.56,54.38) ; C521.2 47.89,55.2 ; C521.2 48.46,54.62 ; 138.51,89.42 C329.2 138.51,90.57 ; C579.1 10.3,34.5 ; C579.1 9.73,35.07 ; C579.1 9.73,33.92 ; 126.25,63.89 R590.2 127.14,63.89 ; 48.65,41.48 C570.2 ; C570.2 49.23,42.05 ; C570.2 49.23,40.91 ; v2(81.61,51.88) 81.74,51.76 C517.2 ; R338.2 117.11,159.21 ; R338.2 115.96,159.21 ; R338.2 116.54,158.64 ; v2(84.56,58.5) C359.1 v2(82.47,58.5) ; v2(103.23,32.29) 103.17,32.34 C592.2 ; C459.1 117.93,65.55 ; C459.1 117.93,63.9 ; C459.1 117.23,64.72 ; 109.04,66.06 U102.2 109.04,64.56 ; 42.56,72.21 C415.1 ; C415.1 43.13,71.64 ; C415.1 43.13,72.79 ; 142.01,41.17 R675.2 142.01,40.26 ; v2(61.47,34.78) 61.57,34.67 C577.2 63.83,34.67 v2(63.91,34.6) ; v2(52.65,67.58) v2(52.65,69.23) ; v2(64.31,73.74) C394.1 v2(66.37,73.74) ; C140.2 v2(58.7,37.42) ; C140.2 57.35,36.65 ; C140.2 57.35,38.18 ; C140.2 v2(56.01,37.42) ; C91.1 v2(90.53,60.66) ; C91.1 89.48,61.36 ; C91.1 v2(88.44,60.66) ; C91.1 89.48,59.96 ; C536.2 159.33,53.1 ; C536.2 159.33,51.96 ; C536.2 158.76,52.53 ; 120.32,72.61 C379.1 119.3,73.31 ; 14.68,82.18 C345.2 ; C345.2 14.68,83.33 ; C345.2 14.11,82.76 ; C448.2 2.36,67.71 ; C448.2 2.36,66.56 ; C448.2 1.79,67.13 ; 153.37,111.77 C306.2 ; C306.2 153.37,112.92 ; C306.2 152.79,112.35 ; C514.2 v2(47.68,56.34) ; C503.2 2.55,59.01 ; C503.2 1.73,59.71 ; C503.2 0.9,59.01 ; 111.01,66.75 C441.2 ; C441.2 112.15,66.75 ; C441.2 111.58,66.18 ; v2(63.33,75.9) C478.1 v2(61.28,75.9) ; 140.38,157.51 U77.4 ; U77.4 140.78,156.75 ; U77.4 141.19,157.51 ; U77.4 140.78,158.27 ; 123.01,128.79 C290.2 122.44,129.36 ; C229.2 106.76,168.93 ; C229.2 105.93,168.23 ; C229.2 107.58,168.23 ; C229.2 107.58,168.93 ; 148.48,42.5 C566.2 ; C566.2 149.05,43.07 ; C566.2 149.62,42.5 ; C446.2 18.43,67.13 ; C446.2 17.86,67.71 ; C446.2 17.86,66.56 ; 128.16,67.9 C430.2 128.73,67.32 ; 16.33,89.55 C331.2 16.33,90.69 ; C435.2 135.71,70.37 ; C435.2 135.71,69.23 ; C435.2 136.28,69.8 ; C628.2 101.4,26.88 101.02,26.49 v1(100.99,26.49) ; v2(52.65,64.4) v2(52.65,62.75) ; 167.14,63.32 R599.1 ; R599.1 167.63,63.77 ; R599.1 167.63,62.88 ; C596.2 v2(74.24,32.08) ; 119.52,101.42 C319.2 ; C319.2 121.17,101.42 ; C319.2 120.35,100.73 ; C228.2 109.36,168.35 ; C228.2 108.53,169.05 ; C228.2 107.71,168.35 ; C407.1 128.85,70.69 128.22,70.69 ; 121.68,34.88 R760.1 122.25,35.45 ; C417.2 36.53,72.79 ; C417.2 35.95,72.21 ; C417.2 36.53,71.64 ; C563.2 48.79,43.26 v2(49.23,43.69) ; 133.87,82.63 R518.2 ; R518.2 134.44,83.2 ; R518.2 135.01,82.63 ; C531.2 12.33,52.78 ; C531.2 11.19,52.78 ; C531.2 11.76,52.21 ; 137.49,89.42 C330.2 137.49,90.57 ; 42.62,51.2 C539.2 42.05,51.77 ; 153.43,109.3 C314.2 ; C314.2 154,109.87 ; C314.2 154,108.73 ; 34.37,53.74 C535.2 34.94,53.16 ; 126,63.89 R591.2 125.11,63.89 ; 44.84,57.48 C511.2 ; C511.2 45.42,56.91 ; C511.2 45.42,58.05 ; C696.2 137.24,70.37 ; C696.2 136.66,69.8 ; C696.2 137.24,69.23 ; C658.1 9.6,17.67 ; C658.1 9.6,16.52 ; C658.1 10.17,17.1 ; 142.01,40.03 C575.2 142.01,39.12 ; 16.33,73.93 C404.2 16.33,75.07 ; 142.8,166.12 P14.6 142.8,163.83 ; C561.2 v2(73,42.62) ; 107.32,162.56 C232.2 108.23,162.56 ; 44.45,176.99 U73.8 43.23,176.99 ; v2(81.61,61.48) v2(81.61,63.13) ; 121.32,102.31 U92.9 123.43,102.31 ; C325.2 22.81,93.36 ; C325.2 21.98,92.66 ; C325.2 23.64,92.66 ; U78.4 136.21,158.27 ; U78.4 136.62,157.51 ; U78.4 135.81,157.51 ; U78.4 136.21,156.75 ; C532.2 6.49,53.04 ; C532.2 5.92,52.47 ; C532.2 5.92,53.61 ; 63.11,41.07 C564.2 62.28,40.38 ; 147.32,42.95 C567.2 148.23,42.95 ; C269.2 125.55,138.7 ; C269.2 126.12,138.13 ; C269.2 124.98,138.13 ; v2(81.61,55.9) v2(81.61,54.24) ; C520.2 80.18,52.45 ; C520.2 79.48,51.63 ; C520.2 78.78,52.45 ; 142.7,109.36 R464.1 ; R464.1 142.13,109.93 ; R464.1 142.24,110.39 ; R464.1 142.24,109.48 ; 146.95,17.86 R702.2 ; R702.2 147.52,18.43 ; R702.2 147.52,17.29 ; 81.04,50.68 C517.2 ; C517.2 81.74,49.85 ; C517.2 82.44,50.68 ; 125.81,99.58 C318.2 ; C318.2 125.81,101.23 ; C318.2 126.51,100.41 ; C565.2 153.43,42.5 ; C565.2 152.29,42.5 ; C565.2 152.86,43.07 ; 42.56,70.94 C422.2 43.13,71.52 ; 4.65,16.52 C659.1 ; C659.1 4.08,17.1 ; C659.1 4.65,17.67 ; 14.68,66.56 C447.2 ; C447.2 14.11,67.13 ; C447.2 14.68,67.71 ; 135.78,66.29 U101.5 133.49,66.29 ; 44.21,51.77 C538.2 43.64,51.2 ; v2(69.29,73.74) C393.1 v2(67.26,73.74) ; C510.2 v2(48.46,58.3) ; 15.32,90.69 C332.2 15.32,89.55 ; C578.2 54.66,43.49 v2(54.66,43.06) ; 7.72,63.83 U104.5 8.89,63.83 ; C380.1 136.98,74.63 ; v2(78.68,75.9) C373.1 v2(80.73,75.9) ; C305.2 147.08,112.98 ; C305.2 146.51,113.55 ; C305.2 146.51,112.41 ; v2(73.22,73.74) C395.1 v2(75.27,73.74) ; v2(85.52,63.58) C92.1 v2(87.59,63.58) ; R463.1 153.57,111.28 ; R463.1 152.66,111.28 ; R463.1 153.57,110.37 ; R463.1 152.66,110.37 ; C95.1 v2(85.52,60.66) ; C95.1 86.56,59.96 ; C95.1 86.56,61.36 ; C95.1 v2(87.59,60.66) ; 10.11,79.9 C351.2 ; C351.2 10.11,81.04 ; C351.2 10.68,80.47 ; 6.91,63.83 U104.2 5.74,63.83 ; v2(83.9,61.86) C387.2 v2(83.9,60.21) ; C354.1 119.84,81.1 120.6,81.87 ; 142.01,41.41 C568.2 142.01,42.32 ; 127.27,63.89 R589.2 128.16,63.89 ; 158.32,68.85 158.32,68.28 157.75,68.28 ; C592.2 101.05,32.34 ; C592.2 101.88,33.04 ; v2(61.65,37.8) v2(63.73,37.8) ; 159.78,112.35 C304.1 159.21,112.92 ; 7.78,79.52 U100.17 7.78,77.23 ; 6.74,61.93 C479.2 ; C479.2 7.32,62.5 ; C479.2 7.32,61.36 ; 109.36,163.02 C231.2 108.79,162.45 ; 121.43,67.43 R570.2 120.54,67.43 ; C618.2 v2(39.7,15.95) ; v2(63.13,73.23) C372.2 v2(61.48,73.23) ; 39.83,71.64 C416.2 ; C416.2 39.83,72.79 ; C416.2 39.26,72.21 ; U101.4 139.46,66.29 ; U101.4 137.17,66.29 ; U101.4 138.32,65.85 ; 106.95,71.2 C421.2 107.77,71.9 ; 158,56.21 C513.1 ; C513.1 158.57,55.64 ; C513.1 158.57,56.78 ; 59.77,176.23 U72.11 59.77,174.2 ; 43.46,81.81 R529.2 42.55,80.9 ; C617.2 v2(51.79,16.11) ; 81.1,50.13 C516.2 81.1,48.48
  BOTTOM w0.381: C432.1 124.89,70.56 124.03,70.56 ; C379.1 120.35,73.28 v2(120.35,72.34) ; C376.1 119.33,76.96 119.33,78.06
  BOTTOM w0.508: C377.1 138.48,78.69 ; C377.1 138.48,75.14 ; C377.1 139.62,76.91 ; C377.1 137.34,76.91 ; 129.36,88.32 C326.1 ; C326.1 132.92,88.32 ; C326.1 131.14,87.17 ; 137.34,72.34 C409.1 ; C409.1 138.48,74.12 ; C409.1 138.48,70.56 ; 126.57,87.17 C327.1 ; C327.1 124.79,88.32 ; C327.1 128.35,88.32 ; C328.1 122,87.66 v2(119.96,87.66) ; C328.1 123.77,88.32 ; C328.1 122,88.98 v2(119.96,88.98) ; C328.1 120.22,88.32 ; C350.1 118.59,81.49 ; C350.1 117.45,83.26 ; C350.1 116.31,81.49 ; C350.1 117.45,79.71 ; C349.1 138.48,83.26 ; C349.1 137.34,81.49 ; C349.1 138.48,79.71 ; C349.1 139.62,81.49 ; 117.45,70.56 C410.1 ; C410.1 118.59,72.34 ; C410.1 117.45,74.12 ; 117.45,78.69 C378.1 117.45,75.14
  BOTTOM w0.762: C63.1 152.35,137.59 ; C63.1 150.57,136.45 ; C63.1 152.35,135.31 ; C63.1 154.13,136.45 ; C62.1 149.05,136.45 ; C62.1 147.27,135.31 ; C62.1 147.27,137.59 ; C62.1 145.49,136.45
  vias: v1(65.53,54.84) v1(74.35,66.86) v1(75.95,50.83) v2(128.73,69.8) v2(128.73,67.01)
